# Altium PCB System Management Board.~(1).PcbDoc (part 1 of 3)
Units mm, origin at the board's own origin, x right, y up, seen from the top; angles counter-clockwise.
Board outline 150 x 110 mm, 4 copper layers (F.Cu, In1.Cu, In2.Cu, B.Cu); 151 components, 121 nets, 513 pads, 536 vias.
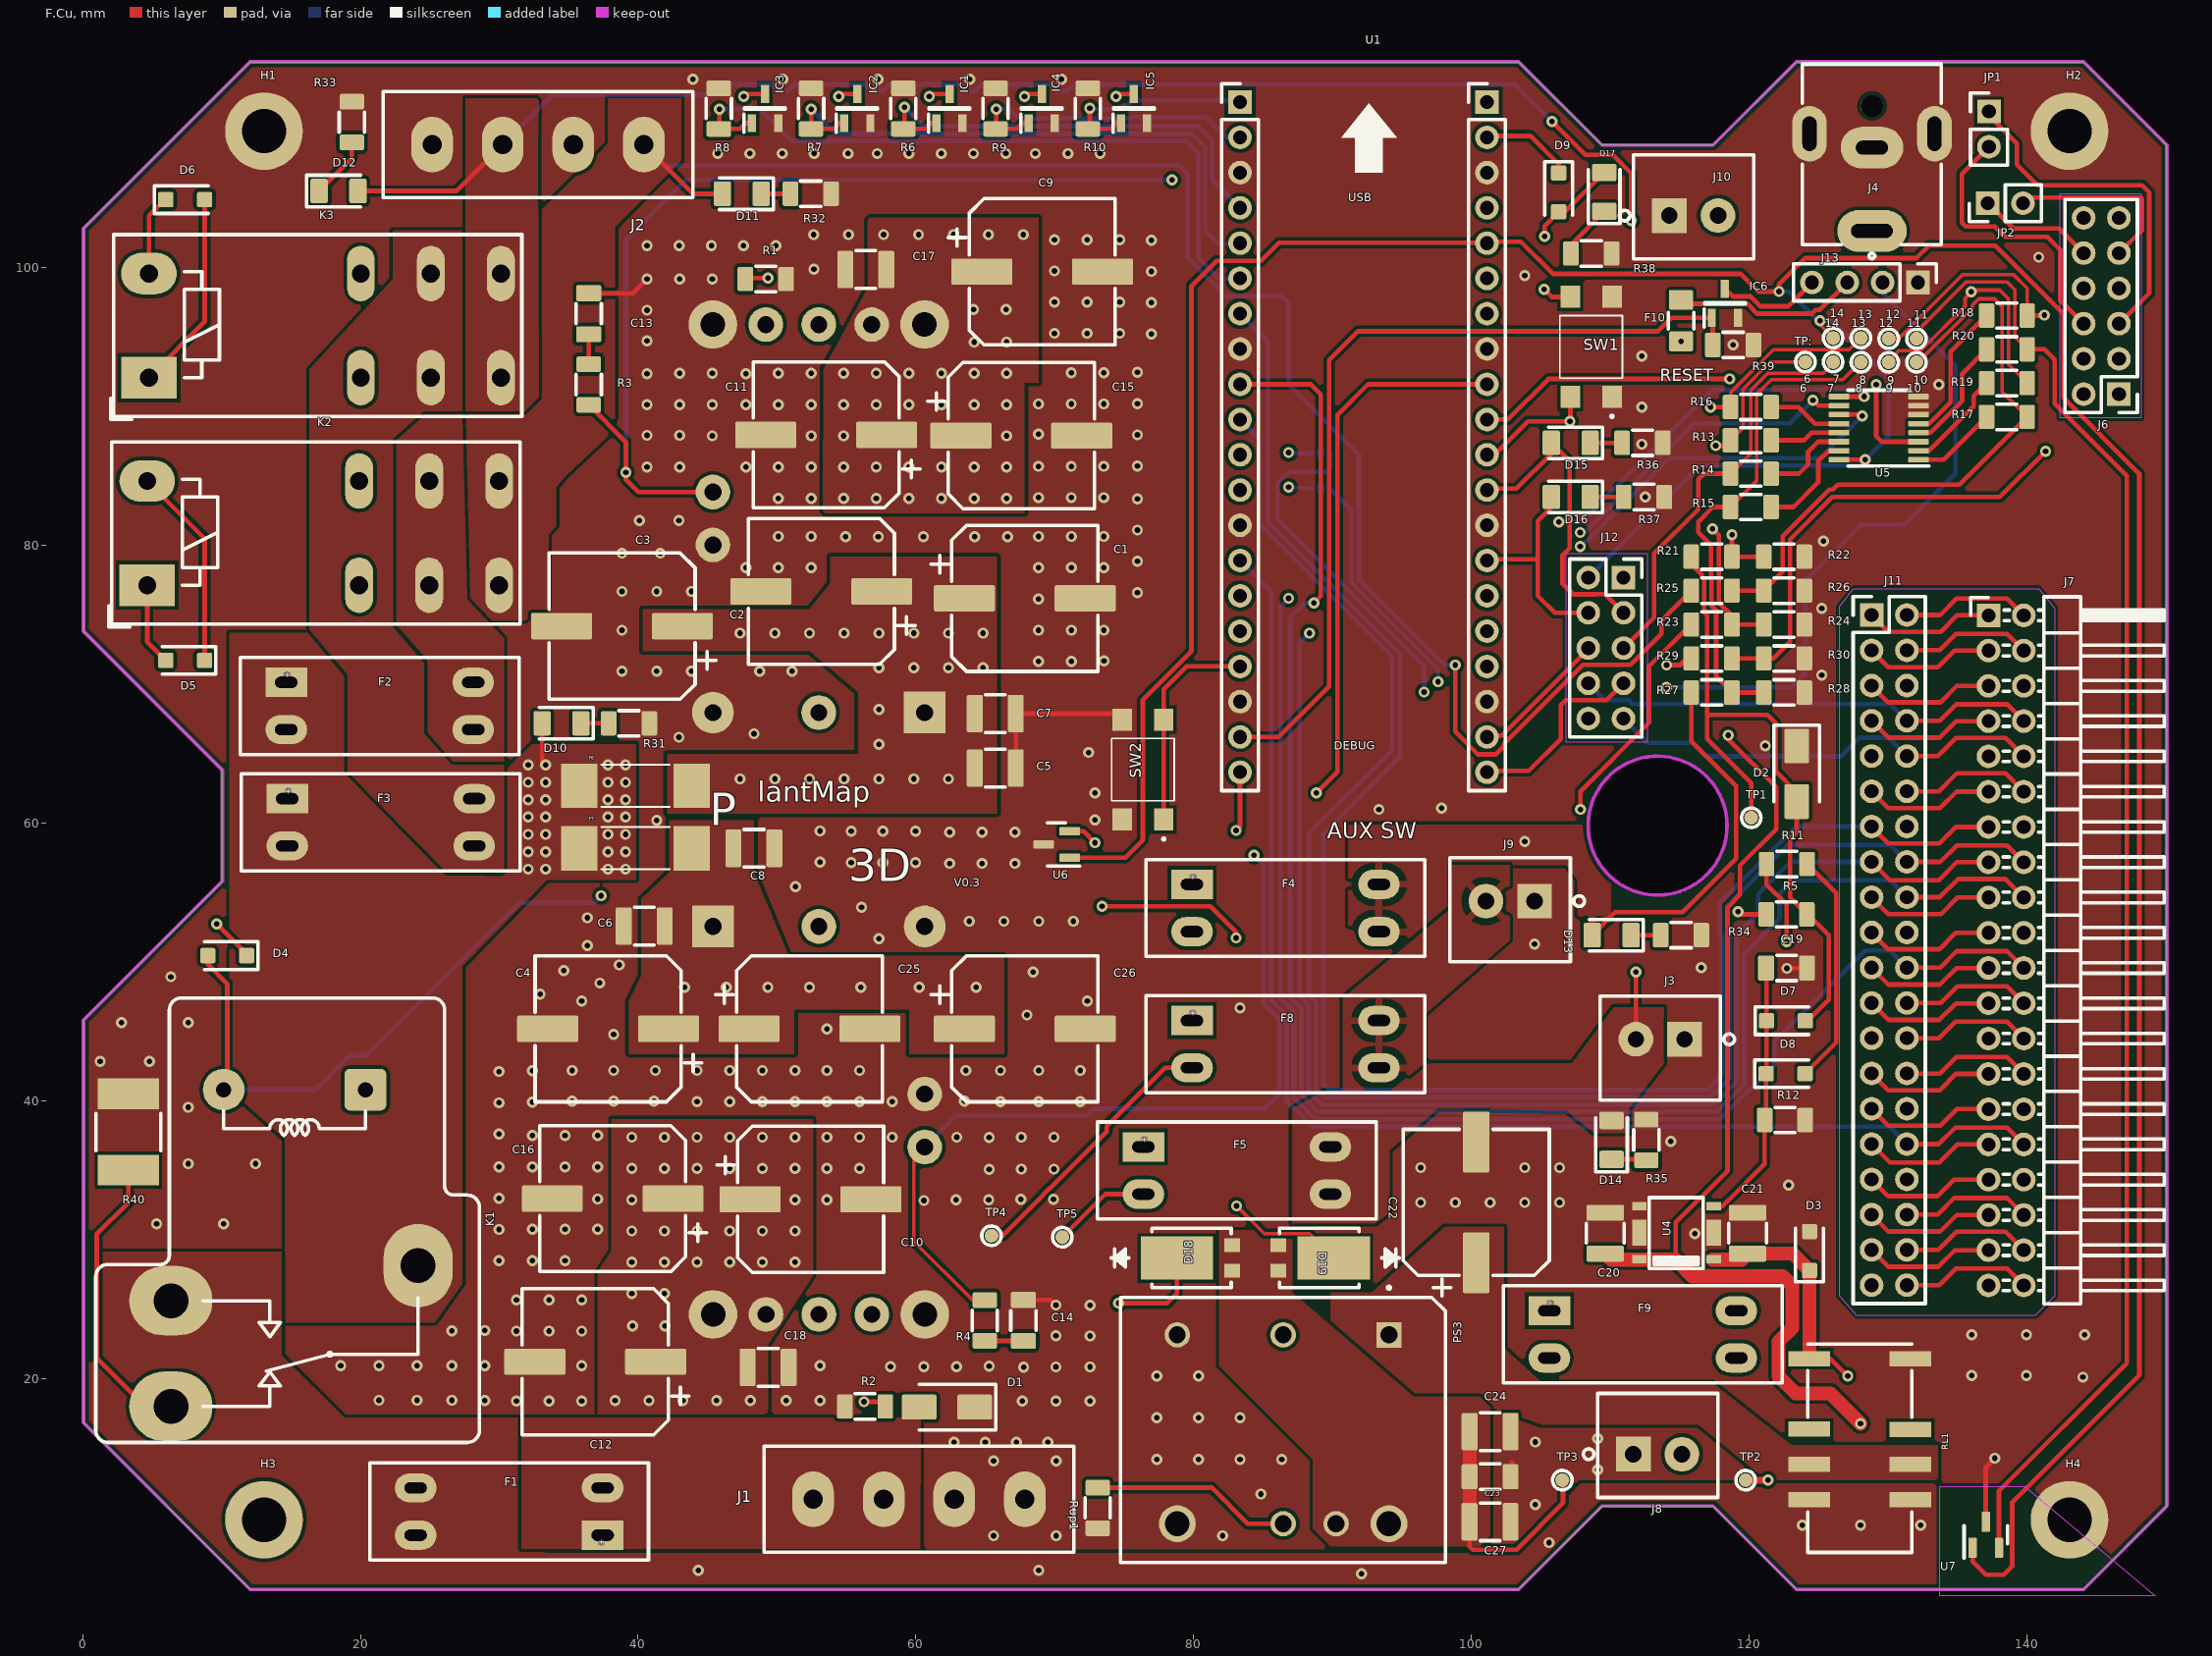
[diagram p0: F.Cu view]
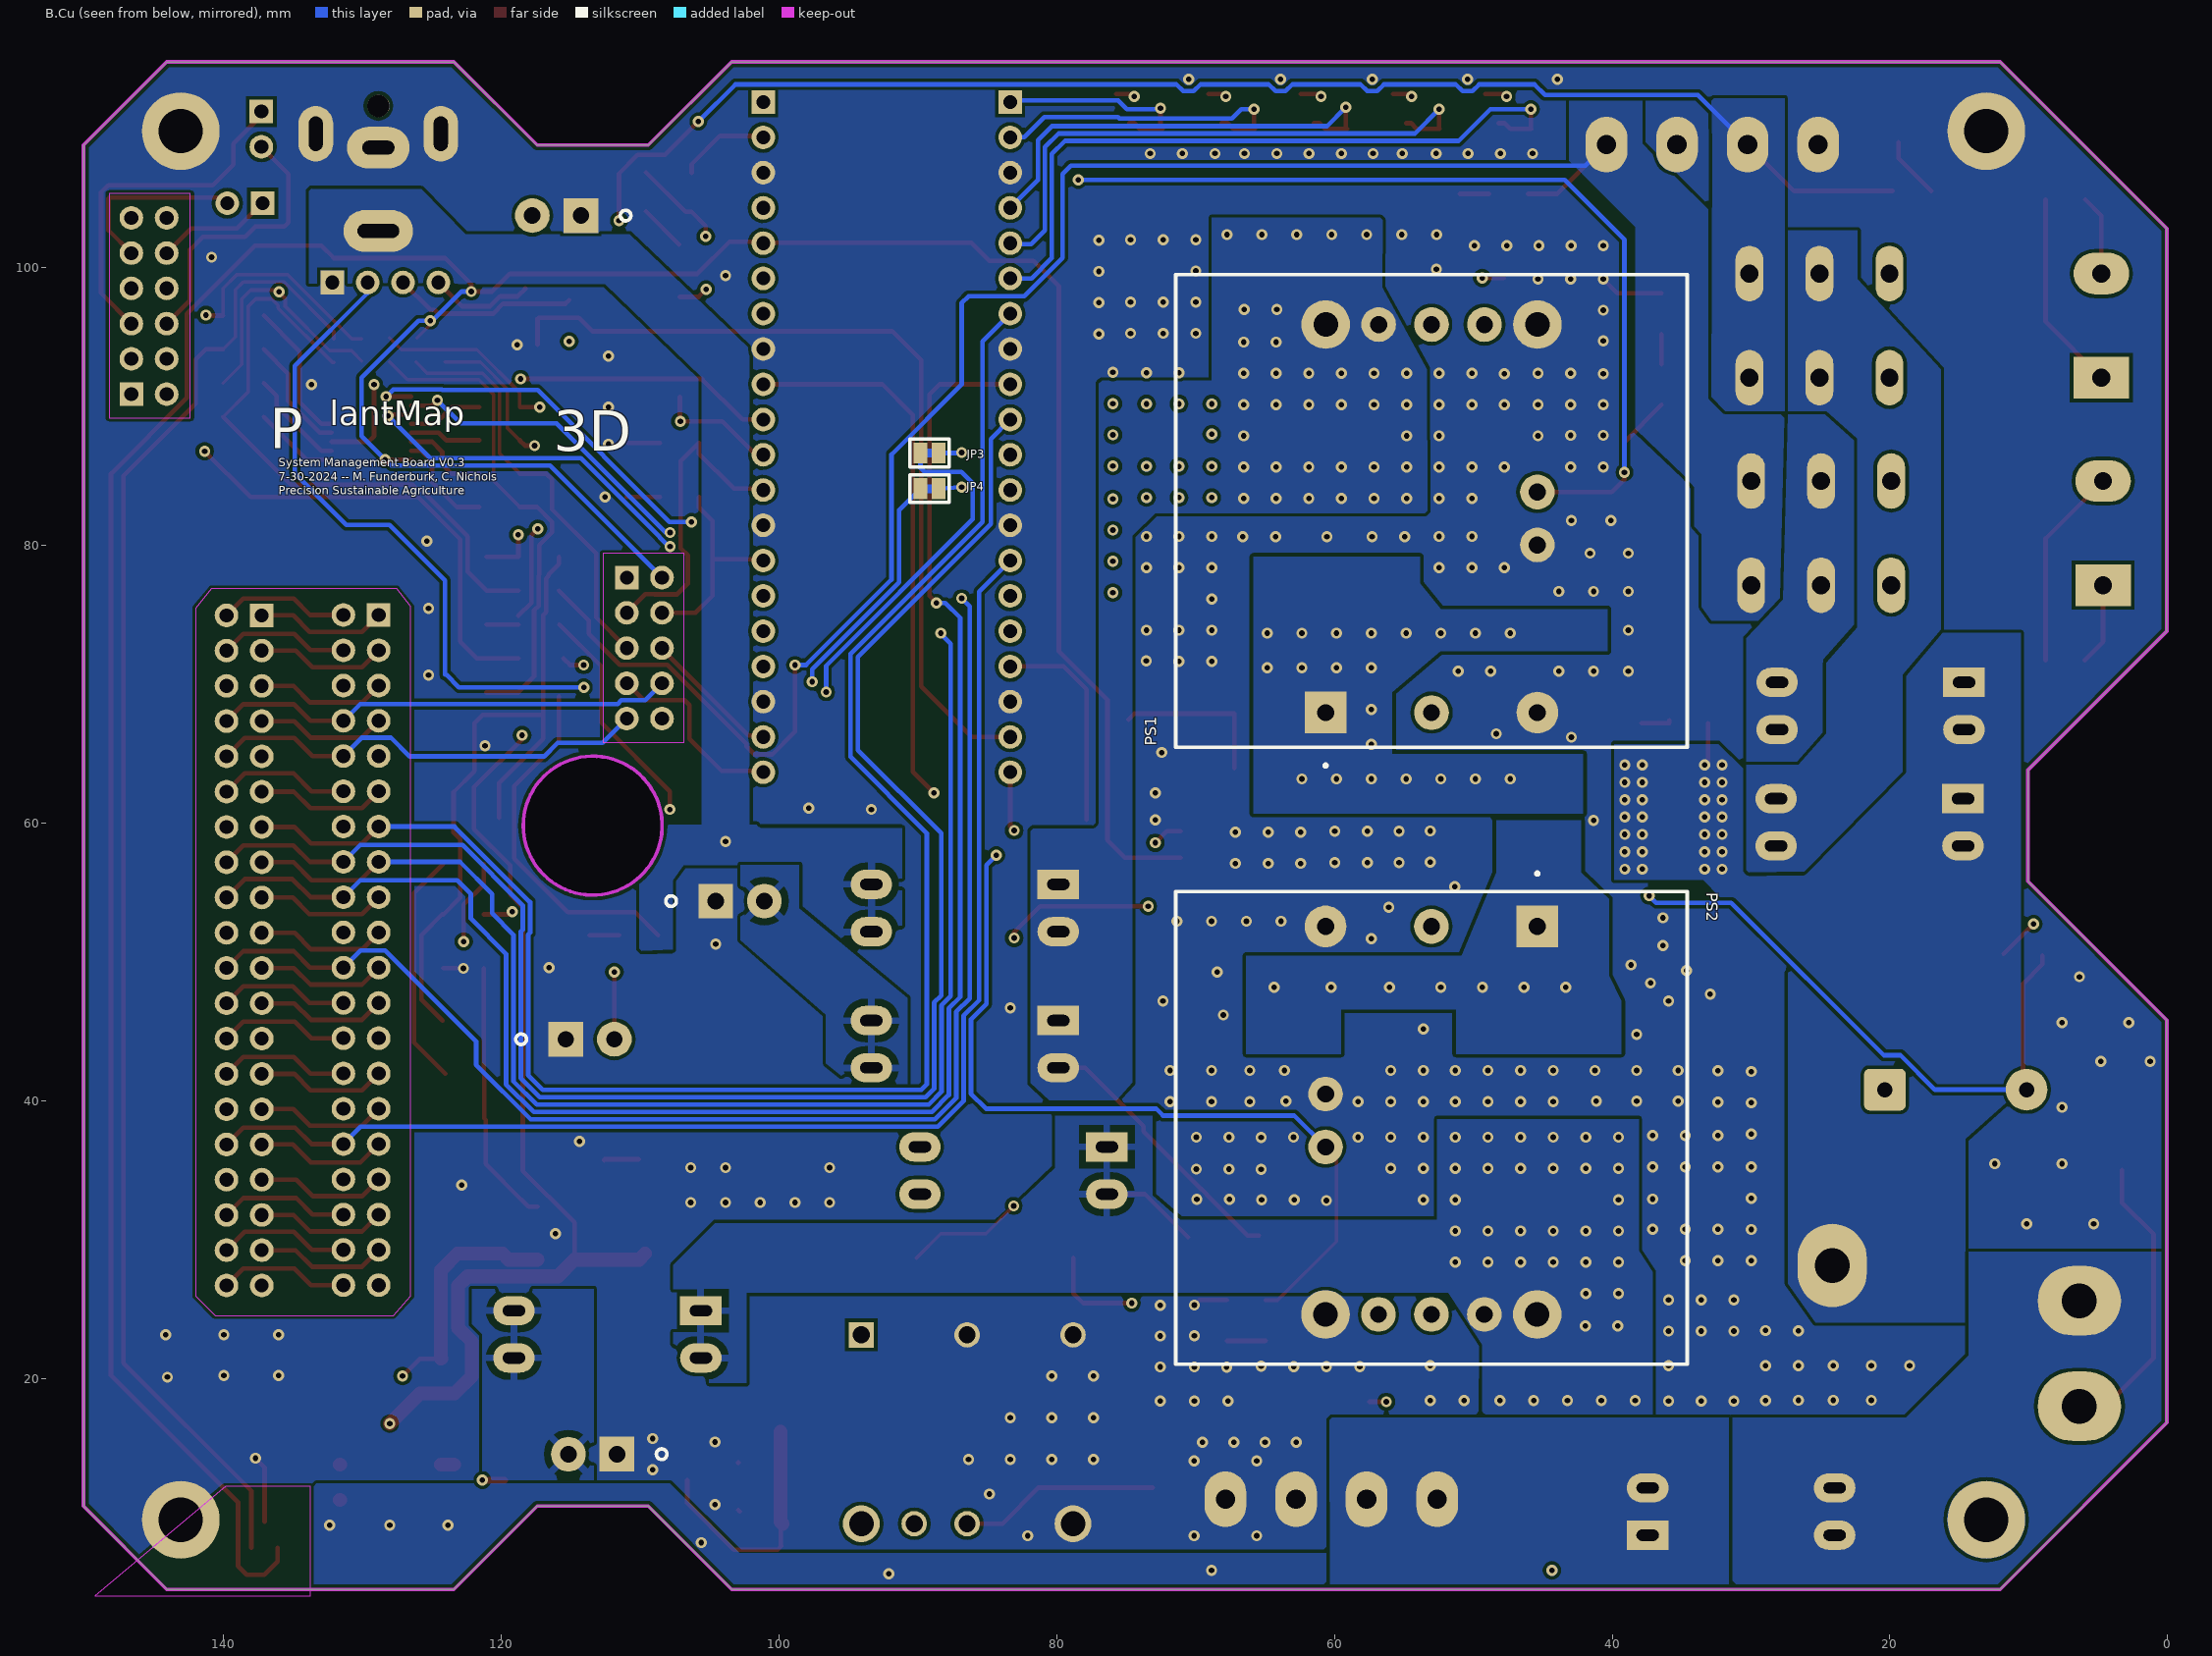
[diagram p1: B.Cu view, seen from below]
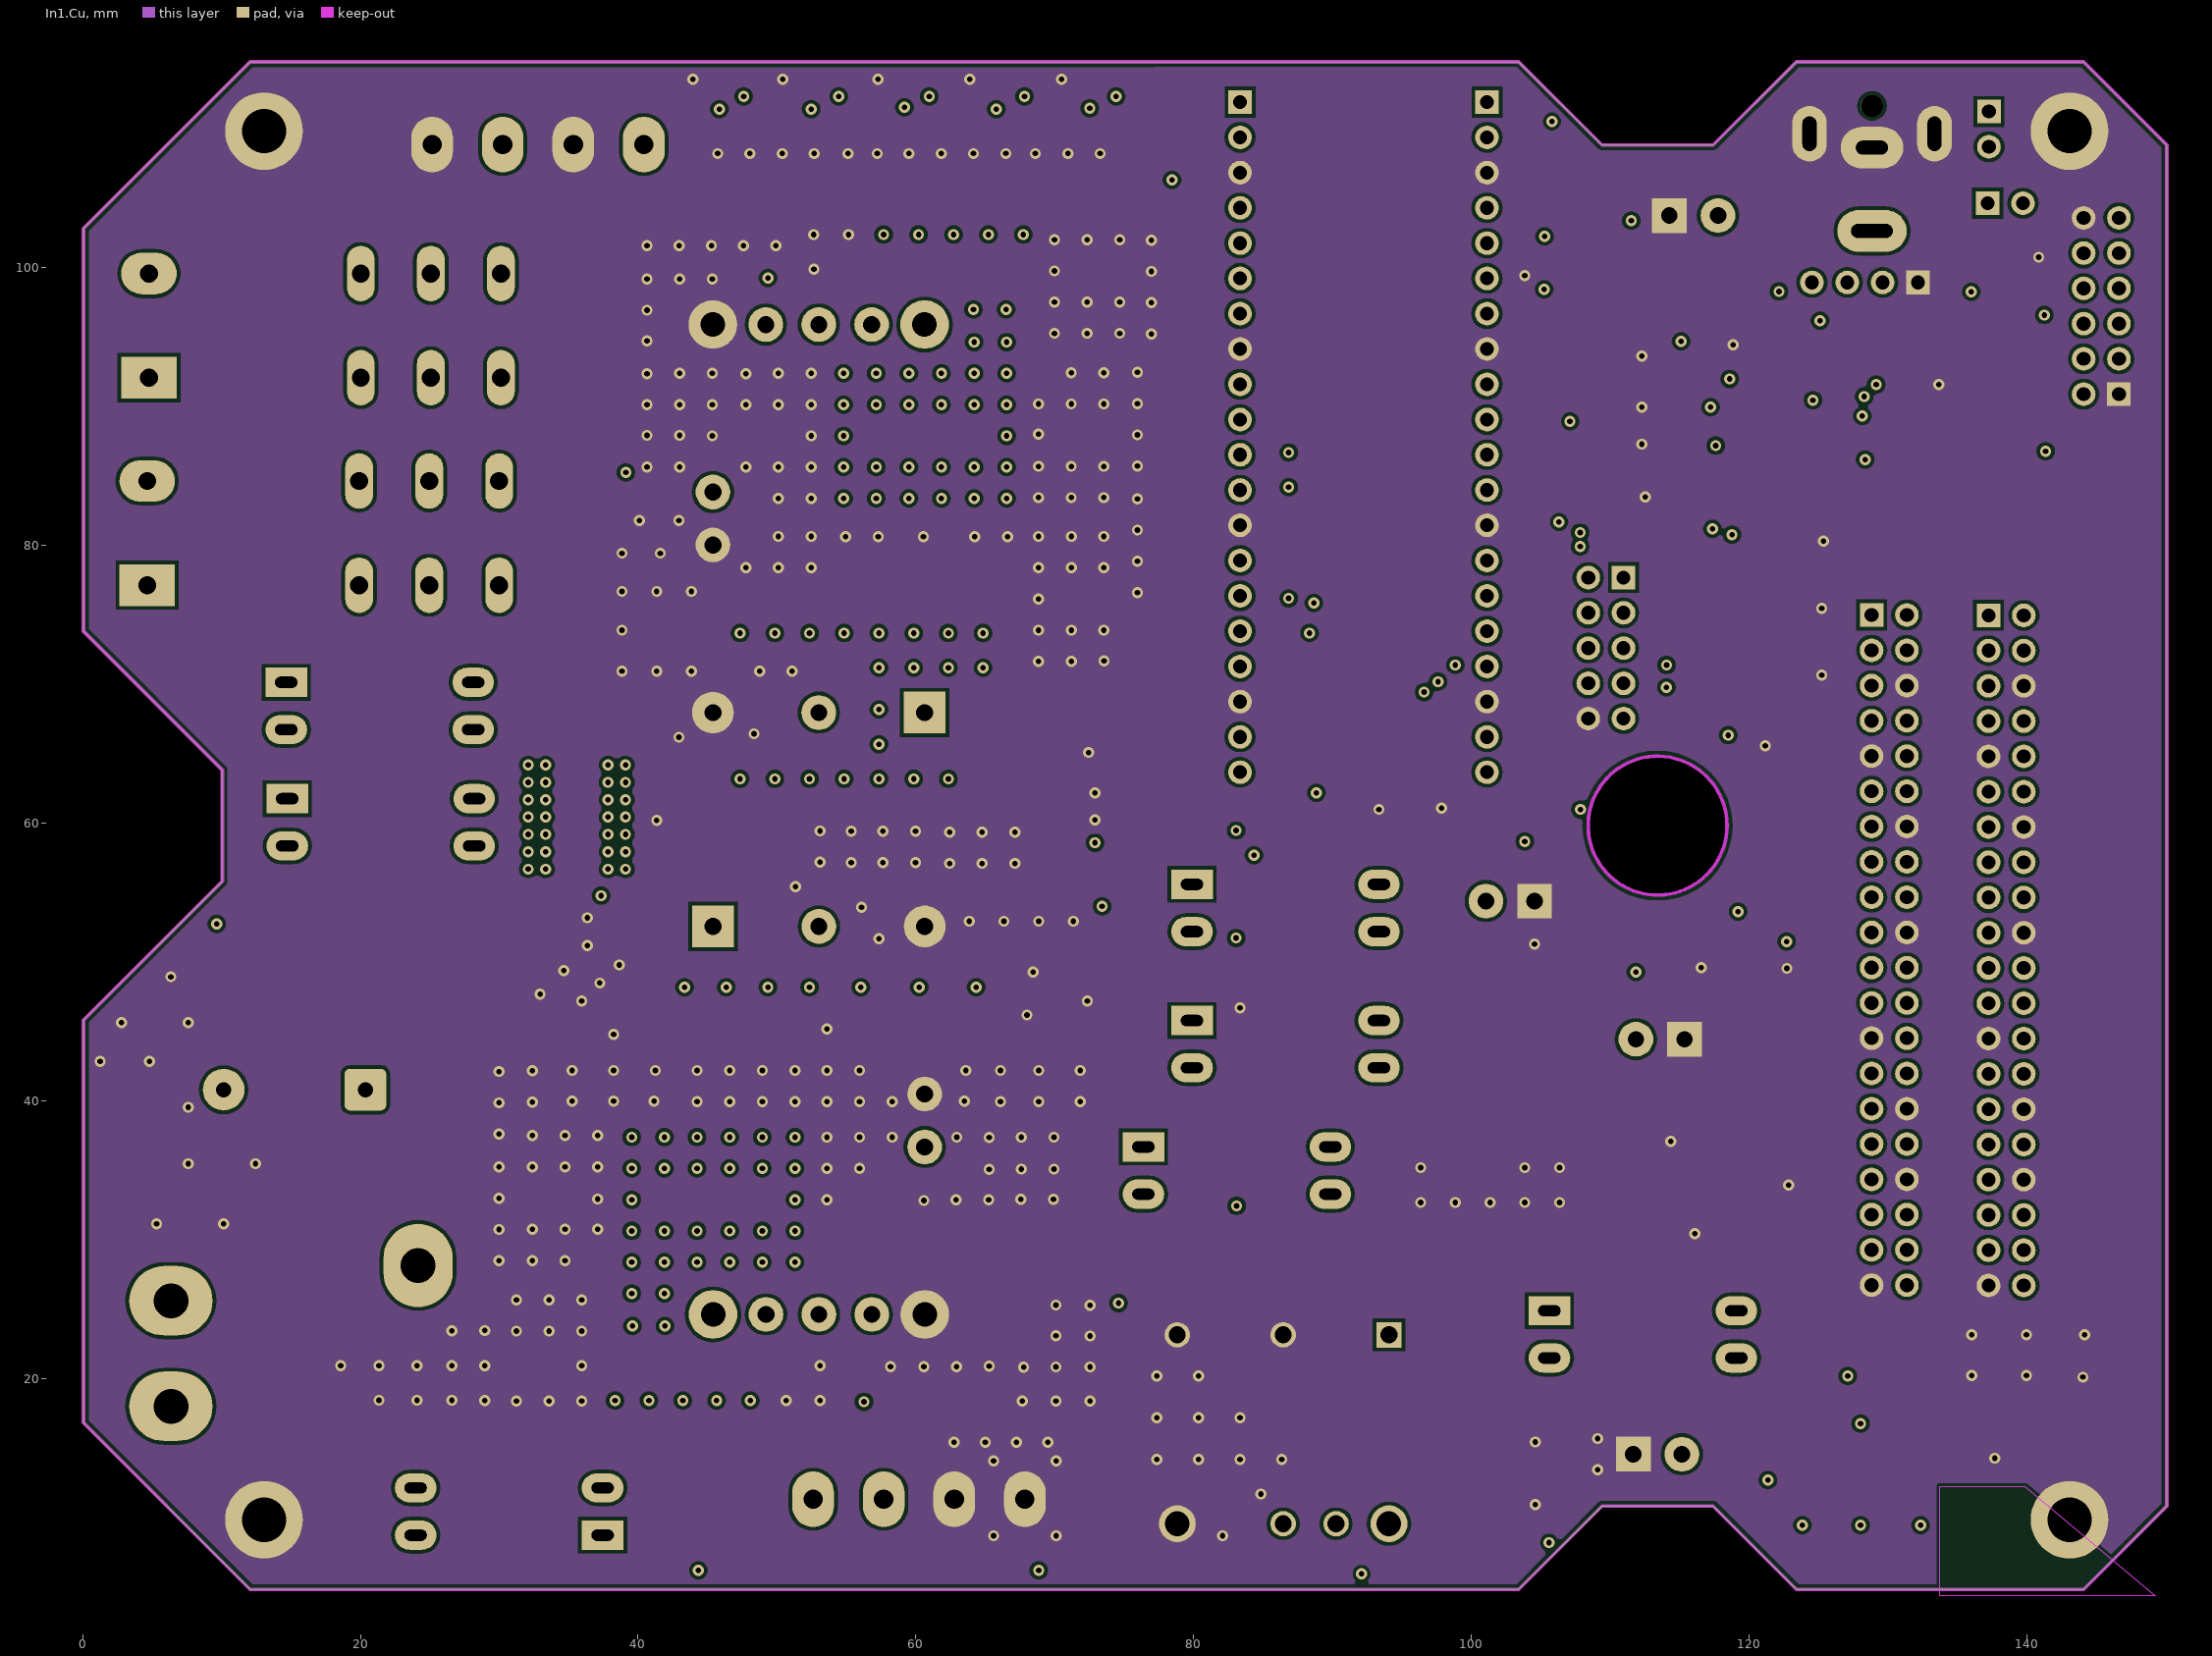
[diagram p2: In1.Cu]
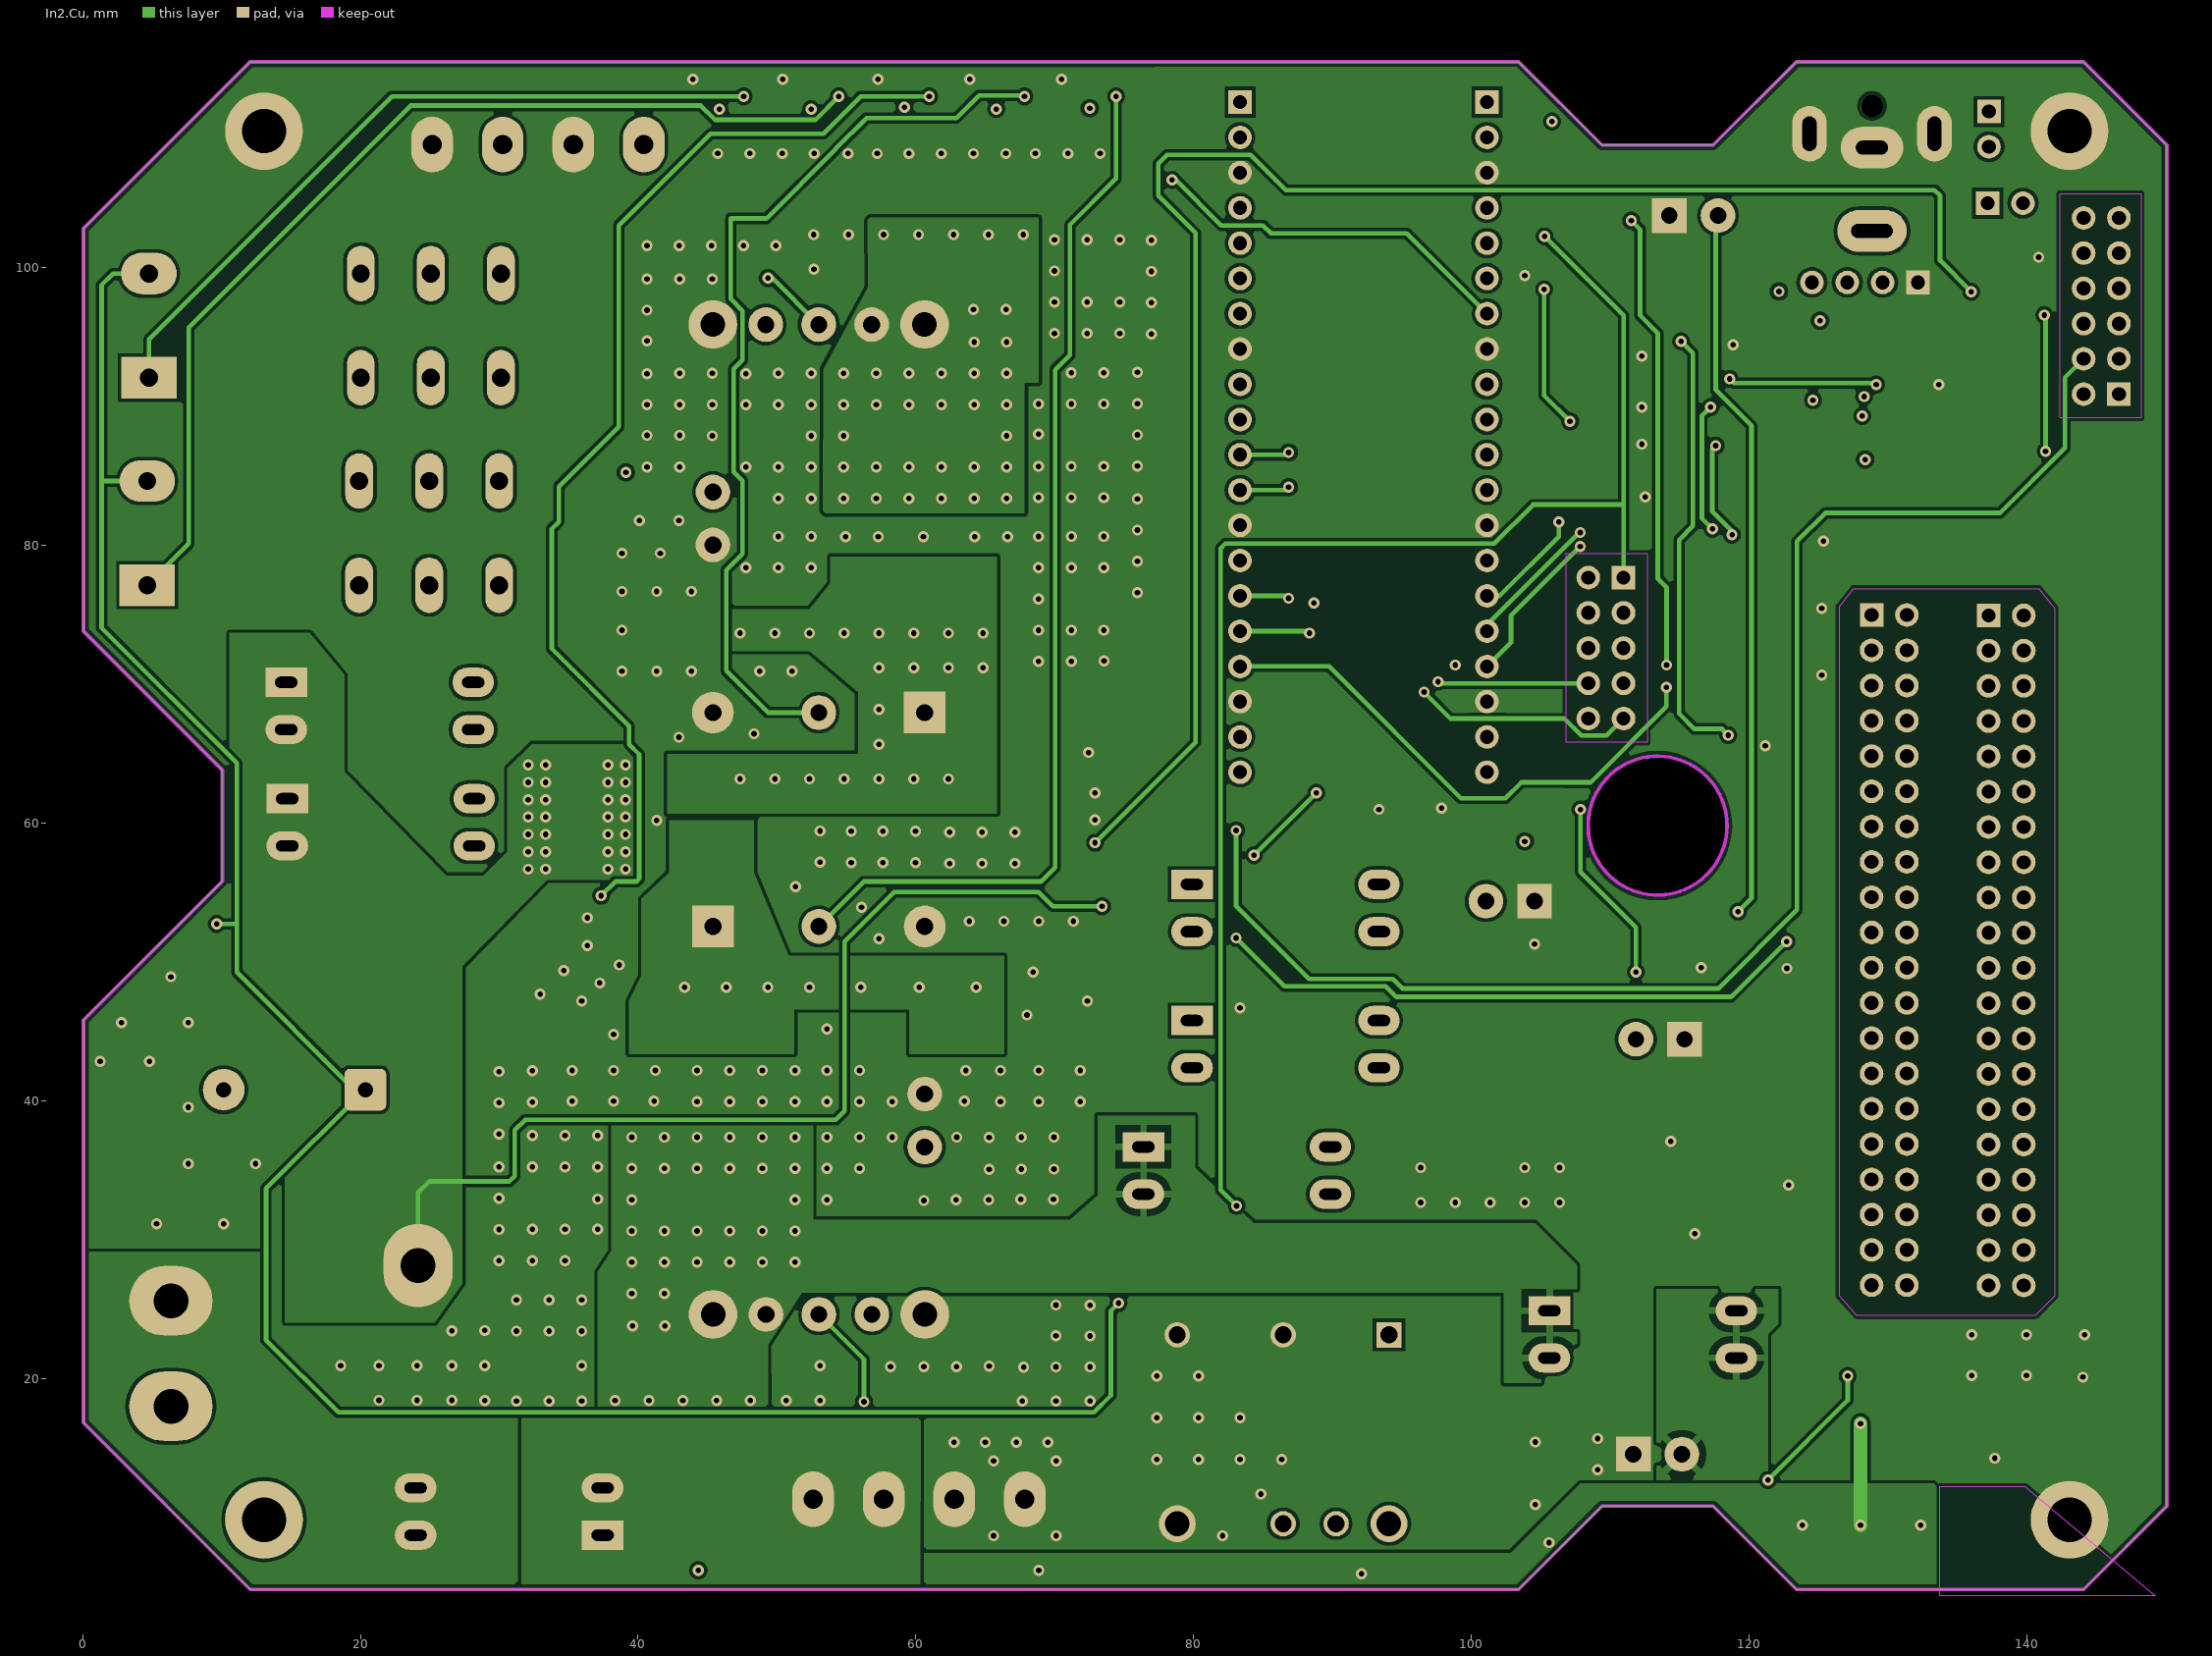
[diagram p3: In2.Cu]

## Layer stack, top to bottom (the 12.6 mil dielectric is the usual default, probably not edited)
F.Mask: solder mask 0.0102, Solder Resist, Dk 3.5
F.Cu: signal copper 0.0356
Dielectric 1: dielectric 0.32, FR-4, Dk 4.8
In1.Cu: signal copper 0.0356
Dielectric2: dielectric 0.32, FR-4, Dk 4.8
In2.Cu: signal copper 0.0356
Dielectric3: dielectric 0.32, FR-4, Dk 4.8
B.Cu: signal copper 0.0356
B.Mask: solder mask 0.0102, Solder Resist, Dk 3.5

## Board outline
109.398,10.821 117.398,10.821 123.398,4.821 144.065,4.821 150.065,10.821 150.065,108.821 144.065,114.821 123.398,114.821 117.398,108.821 109.398,108.821 103.398,114.821 12.065,114.821 0.065,102.821 0.065,73.821 10.065,63.821 10.065,55.821 0.065,45.821 0.065,16.821 12.065,4.821 103.398,4.821 109.398,10.821
cut-out: 108.388,59.821 108.43,59.167 108.558,58.525 108.769,57.904 109.059,57.316 109.423,56.771 109.855,56.278 110.348,55.846 110.893,55.482 111.481,55.192 112.101,54.981 112.744,54.854 113.398,54.811 114.052,54.854 114.695,54.981 115.316,55.192 115.904,55.482 116.449,55.846 116.941,56.278 117.374,56.771 117.738,57.316 118.028,57.904 118.238,58.525 118.366,59.167 118.409,59.821 118.366,60.475 118.238,61.118 118.028,61.739 117.738,62.327 117.374,62.872 116.941,63.365 116.449,63.797 115.904,64.161 115.316,64.451 114.695,64.661 114.052,64.789 113.398,64.832 112.744,64.789 112.101,64.661 111.481,64.451 110.893,64.161 110.348,63.797 109.855,63.365 109.423,62.872 109.059,62.327 108.769,61.739 108.558,61.118 108.43,60.475 108.388,59.821

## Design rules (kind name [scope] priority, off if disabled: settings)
Clearance "Clearence 0.254_Polygon" [InNamedPolygon('F.Cu-/5V Intermediate') OR InNamedPolygon('F.Cu-/i3_Vin') OR InNamedPolygon('F.Cu-/SWITCH PWR OUT PROT') OR InNamedPolygon('F.Cu-GND') OR InNamedPolygon('In2.Cu-GND') OR InNamedPolygon('B.Cu-GND') OR InNamedPolygon('F.Cu-/15v PWR') OR InNamedPolygon('In2.Cu-/15v PWR') OR InNamedPolygon('B.Cu-/15v PWR') OR InNamedPolygon('F.Cu-GND-1') OR InNamedPolygon('In2.Cu-GND-1') OR InNamedPolygon('B.Cu-GND-1') OR InNamedPolygon('F.Cu-/48V PWR') OR InNamedPolygon('In2.Cu-/48V PWR') OR InNamedPolygon('B.Cu-/48V PWR') OR InNamedPolygon('F.Cu-/V_batt+') OR InNamedPolygon('In2.Cu-/V_batt+') OR InNamedPolygon('B.Cu-/V_batt+') OR InNamedPolygon('F.Cu-/V_batt+ PROT') OR InNamedPolygon('In2.Cu-/V_batt+ PROT') OR InNamedPolygon('B.Cu-/V_batt+ PROT') OR InNamedPolygon('F.Cu-/V_batt+ PROT SW') OR InNamedPolygon('In2.Cu-/V_batt+ PROT SW') OR InNamedPolygon('B.Cu-/V_batt+ PROT SW') OR InNamedPolygon('F.Cu-/CPS_IN_PROT') OR InNamedPolygon('In2.Cu-/CPS_IN_PROT') OR InNamedPolygon('B.Cu-/CPS_IN_PROT') OR InNamedPolygon('F.Cu-/V_batt+ PROT-1') OR InNamedPolygon('In2.Cu-/V_batt+ PROT-1') OR InNamedPolygon('B.Cu-/V_batt+ PROT-1') OR InNamedPolygon('F.Cu-/PSPS_IN_PROT') OR InNamedPolygon('In2.Cu-/PSPS_IN_PROT') OR InNamedPolygon('B.Cu-/PSPS_IN_PROT') OR InNamedPolygon('F.Cu-/15V Aux PWR OUT PROT') OR InNamedPolygon('B.Cu-/15V Aux PWR OUT PROT') OR InNamedPolygon('F.Cu-/LIGHT BANK A PROT') OR InNamedPolygon('B.Cu-/LIGHT BANK A PROT') OR InNamedPolygon('F.Cu-/LIGHT BANK A PROT SW') OR InNamedPolygon('B.Cu-/LIGHT BANK A PROT SW') OR InNamedPolygon('F.Cu-/LIGHT BANK B PROT SW') OR InNamedPolygon('B.Cu-/LIGHT BANK B PROT SW') OR InNamedPolygon('F.Cu-/COMP PWR OUT PROT') OR InNamedPolygon('B.Cu-/COMP PWR OUT PROT') OR InNamedPolygon('F.Cu-/LIGHT BANK B PROT') OR InNamedPolygon('B.Cu-/LIGHT BANK B PROT') OR InNamedPolygon('In1.Cu-GND') OR InNamedPolygon('In2.Cu-GND-3') OR InNamedPolygon('In2.Cu-/48V Aux PWR OUT PROT') OR InNamedPolygon('B.Cu-/48V Aux PWR OUT PROT') OR InNamedPolygon('In2.Cu-/48V PWR-1') OR InNamedPolygon('B.Cu-/48V PWR-1') OR InNamedPolygon('B.Cu-/COMP PWR OUT PROT-1') OR InNamedPolygon('B.Cu-/15v PWR-1')] p1: gap=0.254 ignorepadtopadclearanceinfootprint=FALSE
Clearance "Clearence 0.25_Polygon" [InNamedPolygon('In1.Cu-GND-1') OR InNamedPolygon('In2.Cu-GND-2') OR InNamedPolygon('B.Cu-GND-2')] p2: gap=0.25 ignorepadtopadclearanceinfootprint=FALSE
ComponentClearance [All] p1: gap=0.06 collisioncheckmode=3 verticalgap=0.06 showdistances=FALSE
HoleSize [All] p1: absolutevalues=TRUE maxlimit=4 minlimit=0.025 maxpercent=80.000 minpercent=20.000
MinimumSolderMaskSliver [All] p1: minsoldermaskwidth=0
PolygonConnect "Polygon_B.Cu-/15v PWR-1_ConnectDirect" [IsNamedPolygon('B.Cu-/15v PWR-1')] p1: connectstyle=Direct reliefconductorwidth=0.254 reliefentries=4 polygonreliefangle="90 Angle" airgapwidth=0.254
PolygonConnect "Polygon_B.Cu-/COMP PWR OUT PROT-1_ConnectDirect" [IsNamedPolygon('B.Cu-/COMP PWR OUT PROT-1')] p2: connectstyle=Direct reliefconductorwidth=0.254 reliefentries=4 polygonreliefangle="90 Angle" airgapwidth=0.254
PolygonConnect "Polygon_B.Cu-/48V PWR-1_ConnectDirect" [IsNamedPolygon('B.Cu-/48V PWR-1') vs IsVia] p3: connectstyle=Direct reliefconductorwidth=0.254 reliefentries=4 polygonreliefangle="90 Angle" airgapwidth=0.254
PolygonConnect "Polygon_B.Cu-/48V PWR-1_ConnectRelief45" [IsNamedPolygon('B.Cu-/48V PWR-1') vs (IsThruPin or IsSMTPin) and (PadShape_AllLayers = 'Round')] p4: connectstyle=Relief reliefconductorwidth=0.5 reliefentries=4 polygonreliefangle="45 Angle" airgapwidth=0.5
PolygonConnect "Polygon_B.Cu-/48V PWR-1_ConnectRelief90" [IsNamedPolygon('B.Cu-/48V PWR-1') vs (IsThruPin or IsSMTPin) and (PadShape_AllLayers <> 'Round')] p5: connectstyle=Relief reliefconductorwidth=0.5 reliefentries=4 polygonreliefangle="90 Angle" airgapwidth=0.5
PolygonConnect "Polygon_In2.Cu-/48V PWR-1_ConnectDirect" [IsNamedPolygon('In2.Cu-/48V PWR-1') vs IsVia] p6: connectstyle=Direct reliefconductorwidth=0.254 reliefentries=4 polygonreliefangle="90 Angle" airgapwidth=0.254
PolygonConnect "Polygon_In2.Cu-/48V PWR-1_ConnectRelief45" [IsNamedPolygon('In2.Cu-/48V PWR-1') vs (IsThruPin or IsSMTPin) and (PadShape_AllLayers = 'Round')] p7: connectstyle=Relief reliefconductorwidth=0.5 reliefentries=4 polygonreliefangle="45 Angle" airgapwidth=0.5
PolygonConnect "Polygon_In2.Cu-/48V PWR-1_ConnectRelief90" [IsNamedPolygon('In2.Cu-/48V PWR-1') vs (IsThruPin or IsSMTPin) and (PadShape_AllLayers <> 'Round')] p8: connectstyle=Relief reliefconductorwidth=0.5 reliefentries=4 polygonreliefangle="90 Angle" airgapwidth=0.5
PolygonConnect "Polygon_B.Cu-/48V Aux PWR OUT PROT_ConnectDirect" [IsNamedPolygon('B.Cu-/48V Aux PWR OUT PROT') vs IsVia] p9: connectstyle=Direct reliefconductorwidth=0.254 reliefentries=4 polygonreliefangle="90 Angle" airgapwidth=0.254
PolygonConnect "Polygon_B.Cu-/48V Aux PWR OUT PROT_ConnectRelief45" [IsNamedPolygon('B.Cu-/48V Aux PWR OUT PROT') vs (IsThruPin or IsSMTPin) and (PadShape_AllLayers = 'Round')] p10: connectstyle=Relief reliefconductorwidth=0.5 reliefentries=4 polygonreliefangle="45 Angle" airgapwidth=0.5
PolygonConnect "Polygon_B.Cu-/48V Aux PWR OUT PROT_ConnectRelief90" [IsNamedPolygon('B.Cu-/48V Aux PWR OUT PROT') vs (IsThruPin or IsSMTPin) and (PadShape_AllLayers <> 'Round')] p11: connectstyle=Relief reliefconductorwidth=0.5 reliefentries=4 polygonreliefangle="90 Angle" airgapwidth=0.5
PolygonConnect "Polygon_In2.Cu-/48V Aux PWR OUT PROT_ConnectDirect" [IsNamedPolygon('In2.Cu-/48V Aux PWR OUT PROT') vs IsVia] p12: connectstyle=Direct reliefconductorwidth=0.254 reliefentries=4 polygonreliefangle="90 Angle" airgapwidth=0.254
PolygonConnect "Polygon_In2.Cu-/48V Aux PWR OUT PROT_ConnectRelief45" [IsNamedPolygon('In2.Cu-/48V Aux PWR OUT PROT') vs (IsThruPin or IsSMTPin) and (PadShape_AllLayers = 'Round')] p13: connectstyle=Relief reliefconductorwidth=0.5 reliefentries=4 polygonreliefangle="45 Angle" airgapwidth=0.5
PolygonConnect "Polygon_In2.Cu-/48V Aux PWR OUT PROT_ConnectRelief90" [IsNamedPolygon('In2.Cu-/48V Aux PWR OUT PROT') vs (IsThruPin or IsSMTPin) and (PadShape_AllLayers <> 'Round')] p14: connectstyle=Relief reliefconductorwidth=0.5 reliefentries=4 polygonreliefangle="90 Angle" airgapwidth=0.5
PolygonConnect Polygon_In2.Cu-GND-3_ConnectDirect [IsNamedPolygon('In2.Cu-GND-3') vs IsVia] p15: connectstyle=Direct reliefconductorwidth=0.254 reliefentries=4 polygonreliefangle="90 Angle" airgapwidth=0.254
PolygonConnect Polygon_In2.Cu-GND-3_ConnectRelief45 [IsNamedPolygon('In2.Cu-GND-3') vs (IsThruPin or IsSMTPin) and (PadShape_AllLayers = 'Round')] p16: connectstyle=Relief reliefconductorwidth=0.5 reliefentries=4 polygonreliefangle="45 Angle" airgapwidth=0.5
PolygonConnect Polygon_In2.Cu-GND-3_ConnectRelief90 [IsNamedPolygon('In2.Cu-GND-3') vs (IsThruPin or IsSMTPin) and (PadShape_AllLayers <> 'Round')] p17: connectstyle=Relief reliefconductorwidth=0.5 reliefentries=4 polygonreliefangle="90 Angle" airgapwidth=0.5
PolygonConnect Polygon_B.Cu-GND-2_ConnectDirect [IsNamedPolygon('B.Cu-GND-2') vs IsVia] p18: connectstyle=Direct reliefconductorwidth=0.254 reliefentries=4 polygonreliefangle="90 Angle" airgapwidth=0.254
PolygonConnect Polygon_B.Cu-GND-2_ConnectRelief45 [IsNamedPolygon('B.Cu-GND-2') vs (IsThruPin or IsSMTPin) and (PadShape_AllLayers = 'Round')] p19: connectstyle=Relief reliefconductorwidth=0.508 reliefentries=4 polygonreliefangle="45 Angle" airgapwidth=0.508
PolygonConnect Polygon_B.Cu-GND-2_ConnectRelief90 [IsNamedPolygon('B.Cu-GND-2') vs (IsThruPin or IsSMTPin) and (PadShape_AllLayers <> 'Round')] p20: connectstyle=Relief reliefconductorwidth=0.508 reliefentries=4 polygonreliefangle="90 Angle" airgapwidth=0.508
PolygonConnect Polygon_In2.Cu-GND-2_ConnectDirect [IsNamedPolygon('In2.Cu-GND-2') vs IsVia] p21: connectstyle=Direct reliefconductorwidth=0.254 reliefentries=4 polygonreliefangle="90 Angle" airgapwidth=0.254
PolygonConnect Polygon_In2.Cu-GND-2_ConnectRelief45 [IsNamedPolygon('In2.Cu-GND-2') vs (IsThruPin or IsSMTPin) and (PadShape_AllLayers = 'Round')] p22: connectstyle=Relief reliefconductorwidth=0.508 reliefentries=4 polygonreliefangle="45 Angle" airgapwidth=0.508
PolygonConnect Polygon_In2.Cu-GND-2_ConnectRelief90 [IsNamedPolygon('In2.Cu-GND-2') vs (IsThruPin or IsSMTPin) and (PadShape_AllLayers <> 'Round')] p23: connectstyle=Relief reliefconductorwidth=0.508 reliefentries=4 polygonreliefangle="90 Angle" airgapwidth=0.508
PolygonConnect Polygon_In1.Cu-GND-1_ConnectDirect [IsNamedPolygon('In1.Cu-GND-1') vs IsVia] p24: connectstyle=Direct reliefconductorwidth=0.254 reliefentries=4 polygonreliefangle="90 Angle" airgapwidth=0.254
PolygonConnect Polygon_In1.Cu-GND-1_ConnectRelief45 [IsNamedPolygon('In1.Cu-GND-1') vs (IsThruPin or IsSMTPin) and (PadShape_AllLayers = 'Round')] p25: connectstyle=Relief reliefconductorwidth=0.508 reliefentries=4 polygonreliefangle="45 Angle" airgapwidth=0.508
PolygonConnect Polygon_In1.Cu-GND-1_ConnectRelief90 [IsNamedPolygon('In1.Cu-GND-1') vs (IsThruPin or IsSMTPin) and (PadShape_AllLayers <> 'Round')] p26: connectstyle=Relief reliefconductorwidth=0.508 reliefentries=4 polygonreliefangle="90 Angle" airgapwidth=0.508
PolygonConnect Polygon_In1.Cu-GND_ConnectDirect [IsNamedPolygon('In1.Cu-GND')] p27: connectstyle=Direct reliefconductorwidth=0.254 reliefentries=4 polygonreliefangle="90 Angle" airgapwidth=0.254
PolygonConnect "Polygon_B.Cu-/LIGHT BANK B PROT_ConnectDirect" [IsNamedPolygon('B.Cu-/LIGHT BANK B PROT')] p28: connectstyle=Direct reliefconductorwidth=0.254 reliefentries=4 polygonreliefangle="90 Angle" airgapwidth=0.254
PolygonConnect "Polygon_F.Cu-/LIGHT BANK B PROT_ConnectDirect" [IsNamedPolygon('F.Cu-/LIGHT BANK B PROT')] p29: connectstyle=Direct reliefconductorwidth=0.254 reliefentries=4 polygonreliefangle="90 Angle" airgapwidth=0.254
PolygonConnect "Polygon_B.Cu-/COMP PWR OUT PROT_ConnectDirect" [IsNamedPolygon('B.Cu-/COMP PWR OUT PROT') vs IsVia] p30: connectstyle=Direct reliefconductorwidth=0.254 reliefentries=4 polygonreliefangle="90 Angle" airgapwidth=0.254
PolygonConnect "Polygon_B.Cu-/COMP PWR OUT PROT_ConnectRelief45" [IsNamedPolygon('B.Cu-/COMP PWR OUT PROT') vs (IsThruPin or IsSMTPin) and (PadShape_AllLayers = 'Round')] p31: connectstyle=Relief reliefconductorwidth=0.5 reliefentries=4 polygonreliefangle="45 Angle" airgapwidth=0.5
PolygonConnect "Polygon_B.Cu-/COMP PWR OUT PROT_ConnectRelief90" [IsNamedPolygon('B.Cu-/COMP PWR OUT PROT') vs (IsThruPin or IsSMTPin) and (PadShape_AllLayers <> 'Round')] p32: connectstyle=Relief reliefconductorwidth=0.5 reliefentries=4 polygonreliefangle="90 Angle" airgapwidth=0.5
PolygonConnect "Polygon_F.Cu-/COMP PWR OUT PROT_ConnectDirect" [IsNamedPolygon('F.Cu-/COMP PWR OUT PROT') vs IsVia] p33: connectstyle=Direct reliefconductorwidth=0.254 reliefentries=4 polygonreliefangle="90 Angle" airgapwidth=0.254
PolygonConnect "Polygon_F.Cu-/COMP PWR OUT PROT_ConnectRelief45" [IsNamedPolygon('F.Cu-/COMP PWR OUT PROT') vs (IsThruPin or IsSMTPin) and (PadShape_AllLayers = 'Round')] p34: connectstyle=Relief reliefconductorwidth=0.5 reliefentries=4 polygonreliefangle="45 Angle" airgapwidth=0.5
PolygonConnect "Polygon_F.Cu-/COMP PWR OUT PROT_ConnectRelief90" [IsNamedPolygon('F.Cu-/COMP PWR OUT PROT') vs (IsThruPin or IsSMTPin) and (PadShape_AllLayers <> 'Round')] p35: connectstyle=Relief reliefconductorwidth=0.5 reliefentries=4 polygonreliefangle="90 Angle" airgapwidth=0.5
PolygonConnect "Polygon_B.Cu-/LIGHT BANK B PROT SW_ConnectDirect" [IsNamedPolygon('B.Cu-/LIGHT BANK B PROT SW')] p36: connectstyle=Direct reliefconductorwidth=0.254 reliefentries=4 polygonreliefangle="90 Angle" airgapwidth=0.254
PolygonConnect "Polygon_F.Cu-/LIGHT BANK B PROT SW_ConnectDirect" [IsNamedPolygon('F.Cu-/LIGHT BANK B PROT SW')] p37: connectstyle=Direct reliefconductorwidth=0.254 reliefentries=4 polygonreliefangle="90 Angle" airgapwidth=0.254
PolygonConnect "Polygon_B.Cu-/LIGHT BANK A PROT SW_ConnectDirect" [IsNamedPolygon('B.Cu-/LIGHT BANK A PROT SW')] p38: connectstyle=Direct reliefconductorwidth=0.254 reliefentries=4 polygonreliefangle="90 Angle" airgapwidth=0.254
PolygonConnect "Polygon_F.Cu-/LIGHT BANK A PROT SW_ConnectDirect" [IsNamedPolygon('F.Cu-/LIGHT BANK A PROT SW')] p39: connectstyle=Direct reliefconductorwidth=0.254 reliefentries=4 polygonreliefangle="90 Angle" airgapwidth=0.254
PolygonConnect "Polygon_B.Cu-/LIGHT BANK A PROT_ConnectDirect" [IsNamedPolygon('B.Cu-/LIGHT BANK A PROT')] p40: connectstyle=Direct reliefconductorwidth=0.254 reliefentries=4 polygonreliefangle="90 Angle" airgapwidth=0.254
PolygonConnect "Polygon_F.Cu-/LIGHT BANK A PROT_ConnectDirect" [IsNamedPolygon('F.Cu-/LIGHT BANK A PROT')] p41: connectstyle=Direct reliefconductorwidth=0.254 reliefentries=4 polygonreliefangle="90 Angle" airgapwidth=0.254
PolygonConnect "Polygon_B.Cu-/15V Aux PWR OUT PROT_ConnectDirect" [IsNamedPolygon('B.Cu-/15V Aux PWR OUT PROT') vs IsVia] p42: connectstyle=Direct reliefconductorwidth=0.254 reliefentries=4 polygonreliefangle="90 Angle" airgapwidth=0.254
PolygonConnect "Polygon_B.Cu-/15V Aux PWR OUT PROT_ConnectRelief45" [IsNamedPolygon('B.Cu-/15V Aux PWR OUT PROT') vs (IsThruPin or IsSMTPin) and (PadShape_AllLayers = 'Round')] p43: connectstyle=Relief reliefconductorwidth=0.5 reliefentries=4 polygonreliefangle="45 Angle" airgapwidth=0.5
PolygonConnect "Polygon_B.Cu-/15V Aux PWR OUT PROT_ConnectRelief90" [IsNamedPolygon('B.Cu-/15V Aux PWR OUT PROT') vs (IsThruPin or IsSMTPin) and (PadShape_AllLayers <> 'Round')] p44: connectstyle=Relief reliefconductorwidth=0.5 reliefentries=4 polygonreliefangle="90 Angle" airgapwidth=0.5
PolygonConnect "Polygon_F.Cu-/15V Aux PWR OUT PROT_ConnectDirect" [IsNamedPolygon('F.Cu-/15V Aux PWR OUT PROT') vs IsVia] p45: connectstyle=Direct reliefconductorwidth=0.254 reliefentries=4 polygonreliefangle="90 Angle" airgapwidth=0.254
PolygonConnect "Polygon_F.Cu-/15V Aux PWR OUT PROT_ConnectRelief45" [IsNamedPolygon('F.Cu-/15V Aux PWR OUT PROT') vs (IsThruPin or IsSMTPin) and (PadShape_AllLayers = 'Round')] p46: connectstyle=Relief reliefconductorwidth=0.5 reliefentries=4 polygonreliefangle="45 Angle" airgapwidth=0.5
PolygonConnect "Polygon_F.Cu-/15V Aux PWR OUT PROT_ConnectRelief90" [IsNamedPolygon('F.Cu-/15V Aux PWR OUT PROT') vs (IsThruPin or IsSMTPin) and (PadShape_AllLayers <> 'Round')] p47: connectstyle=Relief reliefconductorwidth=0.5 reliefentries=4 polygonreliefangle="90 Angle" airgapwidth=0.5
PolygonConnect Polygon_B.Cu-/PSPS_IN_PROT_ConnectDirect [IsNamedPolygon('B.Cu-/PSPS_IN_PROT')] p48: connectstyle=Direct reliefconductorwidth=0.254 reliefentries=4 polygonreliefangle="90 Angle" airgapwidth=0.254
PolygonConnect Polygon_In2.Cu-/PSPS_IN_PROT_ConnectDirect [IsNamedPolygon('In2.Cu-/PSPS_IN_PROT')] p49: connectstyle=Direct reliefconductorwidth=0.254 reliefentries=4 polygonreliefangle="90 Angle" airgapwidth=0.254
PolygonConnect Polygon_F.Cu-/PSPS_IN_PROT_ConnectDirect [IsNamedPolygon('F.Cu-/PSPS_IN_PROT')] p50: connectstyle=Direct reliefconductorwidth=0.254 reliefentries=4 polygonreliefangle="90 Angle" airgapwidth=0.254
PolygonConnect "Polygon_B.Cu-/V_batt+ PROT-1_ConnectDirect" [IsNamedPolygon('B.Cu-/V_batt+ PROT-1')] p51: connectstyle=Direct reliefconductorwidth=0.254 reliefentries=4 polygonreliefangle="90 Angle" airgapwidth=0.254
PolygonConnect "Polygon_In2.Cu-/V_batt+ PROT-1_ConnectDirect" [IsNamedPolygon('In2.Cu-/V_batt+ PROT-1')] p52: connectstyle=Direct reliefconductorwidth=0.254 reliefentries=4 polygonreliefangle="90 Angle" airgapwidth=0.254
PolygonConnect "Polygon_F.Cu-/V_batt+ PROT-1_ConnectDirect" [IsNamedPolygon('F.Cu-/V_batt+ PROT-1')] p53: connectstyle=Direct reliefconductorwidth=0.254 reliefentries=4 polygonreliefangle="90 Angle" airgapwidth=0.254
PolygonConnect Polygon_B.Cu-/CPS_IN_PROT_ConnectDirect [IsNamedPolygon('B.Cu-/CPS_IN_PROT')] p54: connectstyle=Direct reliefconductorwidth=0.254 reliefentries=4 polygonreliefangle="90 Angle" airgapwidth=0.254
PolygonConnect Polygon_In2.Cu-/CPS_IN_PROT_ConnectDirect [IsNamedPolygon('In2.Cu-/CPS_IN_PROT')] p55: connectstyle=Direct reliefconductorwidth=0.254 reliefentries=4 polygonreliefangle="90 Angle" airgapwidth=0.254
PolygonConnect Polygon_F.Cu-/CPS_IN_PROT_ConnectDirect [IsNamedPolygon('F.Cu-/CPS_IN_PROT')] p56: connectstyle=Direct reliefconductorwidth=0.254 reliefentries=4 polygonreliefangle="90 Angle" airgapwidth=0.254
PolygonConnect "Polygon_B.Cu-/V_batt+ PROT SW_ConnectDirect" [IsNamedPolygon('B.Cu-/V_batt+ PROT SW')] p57: connectstyle=Direct reliefconductorwidth=0.254 reliefentries=4 polygonreliefangle="90 Angle" airgapwidth=0.254
PolygonConnect "Polygon_In2.Cu-/V_batt+ PROT SW_ConnectDirect" [IsNamedPolygon('In2.Cu-/V_batt+ PROT SW')] p58: connectstyle=Direct reliefconductorwidth=0.254 reliefentries=4 polygonreliefangle="90 Angle" airgapwidth=0.254
PolygonConnect "Polygon_F.Cu-/V_batt+ PROT SW_ConnectDirect" [IsNamedPolygon('F.Cu-/V_batt+ PROT SW')] p59: connectstyle=Direct reliefconductorwidth=0.254 reliefentries=4 polygonreliefangle="90 Angle" airgapwidth=0.254
PolygonConnect "Polygon_B.Cu-/V_batt+ PROT_ConnectDirect" [IsNamedPolygon('B.Cu-/V_batt+ PROT')] p60: connectstyle=Direct reliefconductorwidth=0.254 reliefentries=4 polygonreliefangle="90 Angle" airgapwidth=0.254
PolygonConnect "Polygon_In2.Cu-/V_batt+ PROT_ConnectDirect" [IsNamedPolygon('In2.Cu-/V_batt+ PROT')] p61: connectstyle=Direct reliefconductorwidth=0.254 reliefentries=4 polygonreliefangle="90 Angle" airgapwidth=0.254
PolygonConnect "Polygon_F.Cu-/V_batt+ PROT_ConnectDirect" [IsNamedPolygon('F.Cu-/V_batt+ PROT')] p62: connectstyle=Direct reliefconductorwidth=0.254 reliefentries=4 polygonreliefangle="90 Angle" airgapwidth=0.254
PolygonConnect Polygon_B.Cu-/V_batt+_ConnectDirect [IsNamedPolygon('B.Cu-/V_batt+')] p63: connectstyle=Direct reliefconductorwidth=0.254 reliefentries=4 polygonreliefangle="90 Angle" airgapwidth=0.254
PolygonConnect Polygon_In2.Cu-/V_batt+_ConnectDirect [IsNamedPolygon('In2.Cu-/V_batt+')] p64: connectstyle=Direct reliefconductorwidth=0.254 reliefentries=4 polygonreliefangle="90 Angle" airgapwidth=0.254
PolygonConnect Polygon_F.Cu-/V_batt+_ConnectDirect [IsNamedPolygon('F.Cu-/V_batt+')] p65: connectstyle=Direct reliefconductorwidth=0.254 reliefentries=4 polygonreliefangle="90 Angle" airgapwidth=0.254
PolygonConnect "Polygon_B.Cu-/48V PWR_ConnectDirect" [IsNamedPolygon('B.Cu-/48V PWR')] p66: connectstyle=Direct reliefconductorwidth=0.254 reliefentries=4 polygonreliefangle="90 Angle" airgapwidth=0.254
PolygonConnect "Polygon_In2.Cu-/48V PWR_ConnectDirect" [IsNamedPolygon('In2.Cu-/48V PWR')] p67: connectstyle=Direct reliefconductorwidth=0.254 reliefentries=4 polygonreliefangle="90 Angle" airgapwidth=0.254
PolygonConnect "Polygon_F.Cu-/48V PWR_ConnectDirect" [IsNamedPolygon('F.Cu-/48V PWR')] p68: connectstyle=Direct reliefconductorwidth=0.254 reliefentries=4 polygonreliefangle="90 Angle" airgapwidth=0.254
PolygonConnect Polygon_B.Cu-GND-1_ConnectDirect [IsNamedPolygon('B.Cu-GND-1')] p69: connectstyle=Direct reliefconductorwidth=0.254 reliefentries=4 polygonreliefangle="90 Angle" airgapwidth=0.254
PolygonConnect Polygon_In2.Cu-GND-1_ConnectDirect [IsNamedPolygon('In2.Cu-GND-1')] p70: connectstyle=Direct reliefconductorwidth=0.254 reliefentries=4 polygonreliefangle="90 Angle" airgapwidth=0.254
PolygonConnect Polygon_F.Cu-GND-1_ConnectDirect [IsNamedPolygon('F.Cu-GND-1')] p71: connectstyle=Direct reliefconductorwidth=0.254 reliefentries=4 polygonreliefangle="90 Angle" airgapwidth=0.254
PolygonConnect "Polygon_B.Cu-/15v PWR_ConnectDirect" [IsNamedPolygon('B.Cu-/15v PWR')] p72: connectstyle=Direct reliefconductorwidth=0.254 reliefentries=4 polygonreliefangle="90 Angle" airgapwidth=0.254
PolygonConnect "Polygon_In2.Cu-/15v PWR_ConnectDirect" [IsNamedPolygon('In2.Cu-/15v PWR')] p73: connectstyle=Direct reliefconductorwidth=0.254 reliefentries=4 polygonreliefangle="90 Angle" airgapwidth=0.254
PolygonConnect "Polygon_F.Cu-/15v PWR_ConnectDirect" [IsNamedPolygon('F.Cu-/15v PWR')] p74: connectstyle=Direct reliefconductorwidth=0.254 reliefentries=4 polygonreliefangle="90 Angle" airgapwidth=0.254
PolygonConnect Polygon_B.Cu-GND_ConnectDirect [IsNamedPolygon('B.Cu-GND')] p75: connectstyle=Direct reliefconductorwidth=0.254 reliefentries=4 polygonreliefangle="90 Angle" airgapwidth=0.254
PolygonConnect Polygon_In2.Cu-GND_ConnectDirect [IsNamedPolygon('In2.Cu-GND')] p76: connectstyle=Direct reliefconductorwidth=0.254 reliefentries=4 polygonreliefangle="90 Angle" airgapwidth=0.254
PolygonConnect Polygon_F.Cu-GND_ConnectDirect [IsNamedPolygon('F.Cu-GND')] p77: connectstyle=Direct reliefconductorwidth=0.254 reliefentries=4 polygonreliefangle="90 Angle" airgapwidth=0.254
PolygonConnect "Polygon_F.Cu-/SWITCH PWR OUT PROT_ConnectDirect" [IsNamedPolygon('F.Cu-/SWITCH PWR OUT PROT')] p78: connectstyle=Direct reliefconductorwidth=0.254 reliefentries=4 polygonreliefangle="90 Angle" airgapwidth=0.254
PolygonConnect Polygon_F.Cu-/i3_Vin_ConnectDirect [IsNamedPolygon('F.Cu-/i3_Vin')] p79: connectstyle=Direct reliefconductorwidth=0.254 reliefentries=4 polygonreliefangle="90 Angle" airgapwidth=0.254
PolygonConnect "Polygon_F.Cu-/5V Intermediate_ConnectDirect" [IsNamedPolygon('F.Cu-/5V Intermediate')] p80: connectstyle=Direct reliefconductorwidth=0.254 reliefentries=4 polygonreliefangle="90 Angle" airgapwidth=0.254
RoutingVias [All] p1: holewidth=0.711 width=1.27 viastyle="Through Hole" minholewidth=0.711 minwidth=1.27 maxholewidth=0.711 maxwidth=1.27
SilkToSilkClearance [All] p1: silktosilkclearance=0
SilkToSolderMaskClearance [IsPad] p1: minsilkscreentomaskgap=0 clearancetoexposedcopper=TRUE
SolderMaskExpansion [All] p1: expansion=0.102 istentingtop=FALSE
SupplyNets "Schematic Supply Nets" [InNet('GND')] p1: voltage=0.000
Width [All] p1: maxlimit=10 minlimit=0.25 preferedwidth=0.25 minimp=50.000000 maximp=50.000000 favimp=50.000000
25 further rules are at their usual default settings.

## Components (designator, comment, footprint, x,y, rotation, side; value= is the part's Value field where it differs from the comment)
6 "Comment" TESTPOINT_PAD_D1.0MM 124.04,93.205 r90 top value=TestPoint (schematic designator TP6)
7 "Comment" TESTPOINT_PAD_D1.0MM 126.04,93.205 r90 top value=TestPoint (schematic designator TP7)
8 "Comment" TESTPOINT_PAD_D1.0MM 128.04,93.187 r90 top value=TestPoint (schematic designator TP8)
9 "Comment" TESTPOINT_PAD_D1.0MM 130.04,93.187 r270 top value=TestPoint (schematic designator TP9)
10 "Comment" TESTPOINT_PAD_D1.0MM 132.04,93.187 r90 top value=TestPoint (schematic designator TP10)
11 "Comment" TESTPOINT_PAD_D1.0MM 132.04,94.887 r90 top value=TestPoint (schematic designator TP11)
12 "Comment" TESTPOINT_PAD_D1.0MM 130.04,94.887 r90 top value=TestPoint (schematic designator TP12)
13 "Comment" TESTPOINT_PAD_D1.0MM 128.04,94.937 r270 top value=TestPoint (schematic designator TP13)
14 "Comment" TESTPOINT_PAD_D1.0MM 126.04,94.937 r90 top value=TestPoint (schematic designator TP14)
C1 "Comment" CP_ELEC_10X12.6 67.84,76.187 r0 top value=180uF
C2 "Comment" CP_ELEC_10X12.6 53.19,76.687 r180 top value=180uF
C3 "Comment" CP_ELEC_10X12.6 38.84,74.187 r180 top value=180uF
C4 "Comment" CP_ELEC_10X12.6 37.84,45.187 r180 top value=180uF
C5 "Comment" C_1210_3225METRIC 65.715,63.962 r0 top value=10uF
C6 "Comment" C_1210_3225METRIC 40.44,52.587 r180 top value=10uF
C7 "Comment" C_1210_3225METRIC 65.715,67.887 r0 top value=10uF
C8 "Comment" C_1210_3225METRIC 48.34,58.187 r0 top value=10uF
C9 "Comment" CP_ELEC_10X12.6 69.09,99.712 r0 top value=100uF
C10 "Comment" CP_ELEC_10X12.6 52.415,32.912 r0 top value=100uF
C11 "Comment" CP_ELEC_10X12.6 53.54,87.962 r180 top value=100uF
C12 "Comment" CP_ELEC_10X12.6 36.915,21.212 r180 top value=100uF
C13 "Comment" C_1206_3216METRIC 36.44,96.687 r90 top value=0.1uF
C14 "Comment" C_1206_3216METRIC 67.74,24.187 r90 top value=0.1uF
C15 "Comment" CP_ELEC_10X12.6 67.59,87.912 r0 top value=100uF
C16 "Comment" CP_ELEC_10X12.6 38.165,32.962 r180 top value=100uF
C17 "Comment" C_1210_3225METRIC 56.39,99.862 r180 top value=0.1uF
C18 "Comment" C_1210_3225METRIC 49.365,20.812 r0 top value=0.1uF
C19 "Comment" C_1206_3216METRIC 122.682,49.57 r0 top value=0.1uF
C20 "Comment" C_1210_3225METRIC 109.627,30.472 r90 top value=10uF
C21 "Comment" C_1210_3225METRIC 119.877,30.472 r90 top value=10uF
C22 "Comment" CP_ELEC_10X12.6 100.34,32.687 r90 top value=100uF
C23 "Comment" C_1206_3216METRIC 101.34,12.937 r0 top value=0.1uF
C24 "Comment" C_1210_3225METRIC 101.34,16.187 r0 top value=10uF
C25 "Comment" CP_ELEC_10X12.6 52.34,45.187 r0 top value=180uF
C26 "Comment" CP_ELEC_10X12.6 67.84,45.187 r0 top value=180uF
C27 "Comment" C_1210_3225METRIC 101.34,9.687 r0 top value=10uF
D1 "Comment" D_SMA 62.23,17.947 r180 top value=D_TVS
D2 "Comment" D_SMA 123.416,63.554 r270 top value=D_TVS
D3 "Comment" D_SOD-123F 124.34,29.187 r90 top value=D
D4 "Comment" D_SOD-123F 10.414,50.459 r180 top value=D
D5 "Comment" D_SOD-123F 7.39,71.718 r180 top value=D
D6 "Comment" D_SOD-123F 7.39,104.903 r0 top value=D
D7 "Comment" D_SOD-123F 122.636,45.77 r0 top value=D
D8 "Comment" D_SOD-123F 122.617,41.96 r0 top value=D
D9 "Comment" D_SOD-123F 106.274,105.424 r270 top value=D
D10 "Comment" LED_1206_3216METRIC 34.484,67.187 r180 top value=RED
D11 "Comment" LED_1206_3216METRIC 47.46,105.321 r180 top value=RED
D12 "Comment" LED_1206_3216METRIC 18.427,105.522 r0 top value=RED
D13 "Comment" LED_1206_3216METRIC 110.09,51.937 r180 top value=RED
D14 "Comment" LED_1206_3216METRIC 110.09,37.187 r90 top value=RED
D15 "Comment" LED_1206_3216METRIC 107.15,87.388 r180 top value=RED
D16 "Comment" LED_1206_3216METRIC 107.15,83.488 r180 top value=RED
D17 "Comment" LED_1206_3216METRIC 109.56,105.462 r90 top value=RED
D18 "Comment" POWERDI5_DIO 79.84,28.687 r90 top value=D5V
D19 "Comment" POWERDI5_DIO 89.036,28.687 r270 top value=D5V
F1 "Comment" 3557-10 37.445,8.725 r180 top value=3557-10
F2 "Comment" 3557-10 14.665,70.142 r0 top value=3557-10
F3 "Comment" 3557-10 14.735,61.762 r0 top value=3557-10
F4 "Comment" 3557-10 79.878,55.59 r0 top value=3557-10
F5 "Comment" 3557-10 76.378,36.687 r0 top value=3557-10
F6 "Comment" FUSC9830X318N 39.805,62.692 r0 top value=Fuse
F7 "Comment" FUSC9830X318N 39.805,58.192 r0 top value=Fuse
F8 "Comment" 3557-10 79.878,45.787 r0 top value=3557-10
F9 "Comment" 3557-10 105.609,24.888 r0 top value=3557-10
F10 "Comment" FUSE_1206_3216METRIC_PAD1.42X1.75MM_HANDSOLDER 115.09,96.187 r90 top value=Fuse
H1 "Comment" MOUNTINGHOLE_3.2MM_M3_DIN965_PAD 13.065,109.837 r0 top value=MountingHole_Pad
H2 "Comment" MOUNTINGHOLE_3.2MM_M3_DIN965_PAD 143.065,109.837 r0 top value=MountingHole_Pad
H3 "Comment" MOUNTINGHOLE_3.2MM_M3_DIN965_PAD 13.065,9.837 r0 top value=MountingHole_Pad
H4 "Comment" MOUNTINGHOLE_3.2MM_M3_DIN965_PAD 143.065,9.837 r0 top value=MountingHole_Pad
IC1 "Comment" SOT95P237X112-3N 62.414,111.457 r90 top value=SI2318CDS-T1-GE3
IC2 "Comment" SOT95P237X112-3N 55.772,111.457 r90 top value=SI2318CDS-T1-GE3
IC3 "Comment" SOT95P237X112-3N 49.129,111.457 r90 top value=SI2318CDS-T1-GE3
IC4 "Comment" SOT95P237X112-3N 69.057,111.457 r90 top value=SI2318CDS-T1-GE3
IC5 "Comment" SOT95P237X112-3N 75.7,111.457 r90 top value=SI2318CDS-T1-GE3
IC6 "Comment" SOT95P237X112-3N 118.252,97.438 r90 top value=SI2318CDS-T1-GE3
J1 "Comment" 1924321 60.22,11.312 r180 top value=Conn_01x04_Male
J2 "Comment" 1924321 32.79,108.862 r180 top value=Conn_01x04_Male
J3 "Comment" 1843606 111.84,44.437 r180 top value=Conn_01x02_Male
J4 "Comment" CUI_PJ-063BH 128.837,102.644 r90 top value=PJ-063BH
J6 "Comment" PINHEADER_2X06_P2.54MM_VERTICAL 146.616,90.891 r180 top value=Conn_02x06_Counter_Clockwise
J7 "Comment" PINHEADER_2X20_P2.54MM_HORIZONTAL 137.227,74.965 r0 top value=Conn_02x20_Odd_Even
J8 "Comment" 1843606 115.152,14.556 r0 top value=Conn_01x02_Male
J9 "Comment" 1843606 101.04,54.387 r180 top value=Conn_01x02_Male
J10 "Comment" 1843606 117.748,103.751 r0 top value=Conn_01x02_Male
J11 "Comment" PINHEADER_2X20_P2.54MM_VERTICAL 128.808,74.991 r0 top value=Conn_02x20_Odd_Even
J12 "Comment" PINSOCKET_2X05_P2.54MM_VERTICAL 110.949,77.686 r0 top value=Conn_02x05_Top_Bottom
J13 "Comment" PINHEADER_1X04_P2.54MM_VERTICAL 132.14,98.937 r270 top value=Conn_01x04_Female
JP1 "Comment" PINHEADER_1X02_P2.54MM_VERTICAL 137.259,111.244 r0 top value=Jumper_2_Open
JP2 "Comment" PINHEADER_1X02_P2.54MM_VERTICAL 137.169,104.64 r90 top value=Jumper_2_Open
JP3 "Comment" SOLDERJUMPER-2_P1.3MM_BRIDGED_PAD1.0X1.5MM 89.15,86.654 r0 bottom value=Jmp_2_Bridged
JP4 "Comment" SOLDERJUMPER-2_P1.3MM_BRIDGED_PAD1.0X1.5MM 89.15,84.09 r0 bottom value=Jmp_2_Bridged
K1 "Comment" RELAY_SPDT_RAYEX-L90S 15.26,43.347 r270 top value=J115F11CH5VDCS61.5U
K2 "Comment" "BIG PADS - RELAY_SPDT_SCHRACK-RT1-16A-FORMC_RM5MM" 4.655,77.137 r0 top value=J114FL1CS165VDC.41
K3 "Comment" "BIG PADS - RELAY_SPDT_SCHRACK-RT1-16A-FORMC_RM5MM" 4.775,92.082 r0 top value=J114FL1CS165VDC.41
PS1 "Comment" CONV_I7C4W008A120V-0C3-R 60.625,67.962 r270 bottom value=I7C4W008A120V-0C3-R
PS2 "Comment" CONV_I7C4W008A120V-0C3-R 45.395,52.562 r90 bottom value=I7C4W008A120V-0C3-R
PS3 "Comment" CONV_I3A4W008A033V-001-R 86.44,16.299 r270 top value=I3A4W008A033V-001-R
R1 "Comment" R_1206_3216METRIC 49.185,99.182 r0 top value=4.64k
R2 "Comment" R_1206_3216METRIC 56.337,17.994 r180 top value=28
R3 "Comment" R_1206_3216METRIC 36.44,91.587 r270 top value=1k
R4 "Comment" R_1206_3216METRIC 64.96,24.187 r90 top value=1k
R5 "Comment" R_1206_3216METRIC 122.682,53.43 r0 top value=28
R6 "Comment" R_1206_3216METRIC 59.093,111.457 r90 top value=10k
R7 "Comment" R_1206_3216METRIC 52.45,111.457 r90 top value=10k
R8 "Comment" R_1206_3216METRIC 45.808,111.457 r90 top value=10k
R9 "Comment" R_1206_3216METRIC 65.736,111.457 r90 top value=10k
R10 "Comment" R_1206_3216METRIC 72.378,111.457 r90 top value=10k
R11 "Comment" R_1206_3216METRIC 122.704,57.051 r0 top value=10k
R12 "Comment" R_1206_3216METRIC 122.568,38.623 r180 top value=10k
R13 "Comment" R_1206_3216METRIC 120.111,87.567 r0 top value=10k
R14 "Comment" R_1206_3216METRIC 120.111,85.167 r0 top value=10k
R15 "Comment" R_1206_3216METRIC 120.111,82.767 r0 top value=10k
R16 "Comment" R_1206_3216METRIC 120.111,89.967 r0 top value=10k
R17 "Comment" R_1206_3216METRIC 138.549,89.252 r180 top value=10k
R18 "Comment" R_1206_3216METRIC 138.549,96.552 r180 top value=10k
R19 "Comment" R_1206_3216METRIC 138.549,91.685 r180 top value=10k
R20 "Comment" R_1206_3216METRIC 138.549,94.118 r180 top value=10k
R21 "Comment" R_1206_3216METRIC 117.294,79.187 r180 top value=220k
R22 "Comment" R_1206_3216METRIC 122.506,79.187 r0 top value=10k
R23 "Comment" R_1206_3216METRIC 117.294,74.299 r180 top value=220k
R24 "Comment" R_1206_3216METRIC 122.506,74.299 r0 top value=10k
R25 "Comment" R_1206_3216METRIC 117.294,76.743 r180 top value=220k
R26 "Comment" R_1206_3216METRIC 122.506,76.743 r0 top value=10k
R27 "Comment" R_1206_3216METRIC 117.294,69.411 r180 top value=220k
R28 "Comment" R_1206_3216METRIC 122.506,69.411 r0 top value=10k
R29 "Comment" R_1206_3216METRIC 117.294,71.855 r180 top value=220k
R30 "Comment" R_1206_3216METRIC 122.506,71.855 r0 top value=10k
R31 "Comment" R_1206_3216METRIC 39.34,67.187 r0 top value=10k
R32 "Comment" R_1206_3216METRIC 52.431,105.321 r0 top value=10k
R33 "Comment" R_1206_3216METRIC 19.391,110.485 r90 top value=10k
R34 "Comment" R_1206_3216METRIC 115.09,51.937 r0 top value=10k
R35 "Comment" R_1206_3216METRIC 112.59,37.187 r90 top value=10k
R36 "Comment" R_1206_3216METRIC 112.31,87.388 r180 top value=1k
R37 "Comment" R_1206_3216METRIC 112.418,83.488 r180 top value=1k
R38 "Comment" R_1206_3216METRIC 108.63,101.026 r180 top value=1k
R39 "Comment" R_1206_3216METRIC 118.84,94.437 r0 top value=10k
R40 "Comment" RES_3540_TEC 3.302,37.759 r90 top value=180
RL1 "Comment" EE2-5NU 128.048,15.237 r270 top value=EE2-5NU
Rup1 "Comment" R_1206_3216METRIC 73.09,10.687 r90 top value=7.57k
SW1 "Comment" SW_TL3305BF260QG 108.619,94.298 r90 top value=SW_Push
SW2 "Comment" SW_TL3305BF260QG 76.343,63.856 r90 top value=SW_Push
TP1 "Comment" TESTPOINT_PAD_D1.0MM 120.14,60.387 r0 top value="KeySwitch IN"
TP2 "Comment" TESTPOINT_PAD_D1.0MM 119.74,12.687 r0 top value=TestPoint
TP3 "Comment" TESTPOINT_PAD_D1.0MM 106.54,12.687 r0 top value=TestPoint
TP4 "Comment" TESTPOINT_PAD_D1.0MM 65.44,30.287 r0 top value=TestPoint
TP5 "Comment" TESTPOINT_PAD_D1.0MM 70.54,30.187 r0 top value=TestPoint
U1 "Comment" MODULE_SCO915_CUSTOM_HEADERSTYLE 82.487,112.786 r0 top value=SC0915
U4 "Comment" HSOP-6J 114.79,30.537 r90 top value=R1560S501B-E2-FE
U5 "Comment" TSSOP-16_4.4X5MM_P0.65MM 129.329,88.443 r180 top value=74HC4051
U6 "Comment" SOT-23 70.132,58.468 r180 top value=MCP9700T-ETT
U7 "Comment" SOT-23 137.029,8.753 r90 top value=MCP9700T-ETT

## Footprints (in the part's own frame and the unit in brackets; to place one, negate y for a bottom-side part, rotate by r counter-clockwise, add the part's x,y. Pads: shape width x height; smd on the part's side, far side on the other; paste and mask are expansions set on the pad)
3557-10 [mm]
  rect 3x2.108 hole 0.8 slot 1.6 at 0 deg paste-2539.97 mask+0: 1(0,0)
  rrect100% 3x2.108 hole 0.8 slot 1.6 at 0 deg paste-2539.97 mask+0: 2(0,-3.404) 3(13.462,-3.404) 4(13.462,0)
  silkscreen extent -3.3,-5.19 16.76,1.79, body extent -3.37,-5.18 16.63,1.82, height 2.45
1843606 [mm]
  rect 2.5x2.5 hole 1.194 paste-2539.97 mask+0: 1(-3.5,0)
  round 2.5 hole 1.194 paste-2539.97 mask+0: 2(0,0)
  silkscreen extent -7.1,-3.12 2.58,4.38, body extent -5.93,-3.03 2.47,4.22, height 9.2
1924321 [mm]
  rrect100% 3x4 hole 1.4 paste-2539.97 mask+0: 1(-7.62,0) 2(-2.54,0) 3(2.54,0) 4(7.62,0)
  silkscreen extent -11.16,-3.82 11.16,3.8, body extent -11.13,-4.78 11.19,3.82, height 12
"BIG PADS - RELAY_SPDT_SCHRACK-RT1-16A-FORMC_RM5MM" [mm]
  rrect100% 2x4 hole 1.3 paste-2539.97 mask+0: 11(20.3,0) 11(20.3,7.5) 12(15.26,0) 12(15.26,7.5) 14(25.34,0) 14(25.34,7.5)
  rect 4x3 hole 1.3 paste-2539.97 mask+0: A1(0,0)
  rrect100% 4x3 hole 1.3 paste-2539.97 mask+0: A2(0,7.5)
  silkscreen extent -2.75,-3 26.85,10.3, body extent -2.34,-2.77 26.85,10.19, height 12
C_1206_3216METRIC [mm]
  rrect22% 1.15x1.8 smd mask+0: 1(-1.475,0) 2(1.475,0)
  silkscreen extent -0.71,-0.91 0.71,0.91
C_1210_3225METRIC [mm]
  rrect22% 1.15x2.7 smd mask+0: 1(-1.475,0) 2(1.475,0)
  silkscreen extent -0.71,-1.36 0.71,1.36
CONV_I3A4W008A033V-001-R [mm]
  rect 1.83x1.83 hole 1.22 paste-2539.97 mask+0.102: 1(-6.85,7.62)
  round 1.83 hole 1.22 paste-2539.97 mask+0.102: 2(-6.85,0) 3(-6.85,-7.62) 6(6.75,0) 7(6.75,3.81)
  round 2.655 hole 1.77 paste-2539.97 mask+0.102: 4(6.75,-7.62) 8(6.75,7.62)
  silkscreen extent -10.35,-11.7 9.55,11.7, body extent -9.51,-11.72 9.54,11.65, height 9.76
CONV_I7C4W008A120V-0C3-R [mm]
  rect 3x3 hole 1.22 paste-2539.97 mask+0: 1(0,0)
  round 2.5 hole 1.22 paste-2539.97 mask+0: 2(0,7.62) 5(-27.94,11.43) 6(-27.94,7.62) 7(-27.94,3.81) 32(-12.07,15.24) 34(-15.88,15.24)
  round 3 hole 1.22 paste-2539.97 mask+0: 3(0,15.24)
  round 3.5 hole 1.77 paste-2539.97 mask+0: 4(-27.94,15.24) 8(-27.94,0)
  silkscreen extent -31.54,-10.8 3.91,26.03, body extent -31.5,-10.79 2.54,26.04, height 13.46
CP_ELEC_10X12.6 [mm]
  rrect13% 4.4x1.9 smd mask+0: 1(-4.35,0) 2(4.35,0)
  silkscreen extent -6.75,-5.26 5.26,5.26
CUI_PJ-063BH [mm]
  rrect100% 3x5 hole 3 slot 1 at 0 deg paste-2539.97 mask+0: 1(0,0)
  rrect100% 3x4.5 hole 2.3 slot 1 at 0 deg paste-2539.97 mask+0: 2(6,0)
  rrect100% 4x2.5 hole 1 slot 2.5 at 0 deg paste-2539.97 mask+0: S1(7,4.5) S2(7,-4.5)
  round 1.6 hole 1.6 paste-2539.97 mask+0: Un1(9,0)
  silkscreen extent -2,-5 12,5, body extent -0.96,-5.52 12.04,4.78, height 9
D_SMA [mm]
  rrect14% 2.5x1.8 smd mask+0: 1(-2,0) 2(2,0)
  silkscreen extent -3.51,-1.65 2,1.65
D_SOD-123F [mm]
  rrect23% 1.1x1.1 smd mask+0: 1(-1.4,0) 2(1.4,0)
  silkscreen extent -2.21,-1 1.65,1
EE2-5NU [mm]
  rect 1.1x3 smd mask+0: +(-6.198,-3.728) -(-6.193,3.55) C1(1.422,-3.728) C2(1.427,3.55) NC1(-1.118,-3.728) NC2(-1.113,3.55) NO1(3.962,-3.728) NO2(3.967,3.55)
  silkscreen extent -7.25,-3.84 7.76,3.66, body extent -7.52,-4.85 7.48,4.65, height 10
FUSC9830X318N [mm]
  rect 2.62x3.2 smd mask+0: 1(-4.047,0) 2(4.047,0)
  silkscreen extent -2.47,-1.52 2.47,1.52, body extent -4.85,-1.63 4.95,1.55, height 2.83
FUSE_1206_3216METRIC_PAD1.42X1.75MM_HANDSOLDER [mm]
  rrect18% 1.425x1.75 smd mask+0: 1(-1.488,0) 2(1.488,0)
  silkscreen extent -0.6,-0.91 0.6,0.91
HSOP-6J [mm]
  rect 0.6x1.05 smd mask+0: 1(-1.93,-2.65) 3(1.88,-2.65) 4(1.88,2.7) 6(-1.93,2.7)
  rect 1.9x1.05 smd mask+0: 2(-0.025,-2.65) 5(-0.025,2.7)
  silkscreen extent -2.62,-1.9 2.5,2, body extent -2.48,-3.03 2.54,2.97, height 1.65
LED_1206_3216METRIC [mm]
  rrect20% 1.25x1.75 smd mask+0: 1(-1.4,0) 2(1.4,0)
  silkscreen extent -2.28,-1.13 1.6,1.13
MODULE_SCO915_CUSTOM_HEADERSTYLE [mm]
  rect 1.7x1.7 hole 1 paste-2539.97 mask+0: 1(0.853,-0.859) 40(18.633,-0.859)
  rrect100% 1.7x1.7 hole 1 paste-2539.97 mask+0: 2(0.853,-3.399) 3(0.853,-5.939) 4(0.853,-8.479) 5(0.853,-11.019) 6(0.853,-13.559) 7(0.853,-16.099) 8(0.853,-18.639) 9(0.853,-21.179) 10(0.853,-23.719) 11(0.853,-26.259) 12(0.853,-28.799) 13(0.853,-31.339) 14(0.853,-33.879) 15(0.853,-36.419) 16(0.853,-38.959) 17(0.853,-41.499) 18(0.853,-44.039) 19(0.853,-46.579) 20(0.853,-49.119) 21(18.633,-49.119) 22(18.633,-46.579) 23(18.633,-44.039) 24(18.633,-41.499) 25(18.633,-38.959) 26(18.633,-36.419) 27(18.633,-33.879) 28(18.633,-31.339) 29(18.633,-28.799) 30(18.633,-26.259) 31(18.633,-23.719) 32(18.633,-21.179) 33(18.633,-18.639) 34(18.633,-16.099) 35(18.633,-13.559) 36(18.633,-11.019) 37(18.633,-8.479) 38(18.633,-5.939) 39(18.633,-3.399)
  silkscreen extent -0.48,-50.45 19.96,0.47
MOUNTINGHOLE_3.2MM_M3_DIN965_PAD [mm]
  round 5.6 hole 3.2 paste-2539.97 mask+0: 1(0,0)
PINHEADER_1X02_P2.54MM_VERTICAL [mm]
  rect 1.7x1.7 hole 1 paste-2539.97 mask+0: 1(0,0)
  rrect100% 1.7x1.7 hole 1 paste-2539.97 mask+0: 2(0,-2.54)
  silkscreen extent -1.33,-3.87 1.33,1.33
PINHEADER_1X04_P2.54MM_VERTICAL [mm]
  rect 1.7x1.7 hole 1 paste-2539.97 mask+0: 1(0,0)
  rrect100% 1.7x1.7 hole 1 paste-2539.97 mask+0: 2(0,-2.54) 3(0,-5.08) 4(0,-7.62)
  silkscreen extent -1.33,-8.95 1.33,1.33
PINHEADER_2X06_P2.54MM_VERTICAL [mm]
  rect 1.7x1.7 hole 1 paste-2539.97 mask+0: 1(0,0)
  rrect100% 1.7x1.7 hole 1 paste-2539.97 mask+0: 2(2.54,0) 3(0,-2.54) 4(2.54,-2.54) 5(0,-5.08) 6(2.54,-5.08) 7(0,-7.62) 8(2.54,-7.62) 9(0,-10.16) 10(2.54,-10.16) 11(0,-12.7) 12(2.54,-12.7)
  silkscreen extent -1.33,-14.03 3.87,1.33
PINHEADER_2X20_P2.54MM_HORIZONTAL [mm]
  rect 1.7x1.7 hole 1 paste-2539.97 mask+0: 1(0,0)
  rrect100% 1.7x1.7 hole 1 paste-2539.97 mask+0: 2(2.54,0) 3(0,-2.54) 4(2.54,-2.54) 5(0,-5.08) 6(2.54,-5.08) 7(0,-7.62) 8(2.54,-7.62) 9(0,-10.16) 10(2.54,-10.16) 11(0,-12.7) 12(2.54,-12.7) 13(0,-15.24) 14(2.54,-15.24) 15(0,-17.78) 16(2.54,-17.78) 17(0,-20.32) 18(2.54,-20.32) 19(0,-22.86) 20(2.54,-22.86) 21(0,-25.4) 22(2.54,-25.4) 23(0,-27.94) 24(2.54,-27.94) 25(0,-30.48) 26(2.54,-30.48) 27(0,-33.02) 28(2.54,-33.02) 29(0,-35.56) 30(2.54,-35.56) 31(0,-38.1) 32(2.54,-38.1) 33(0,-40.64) 34(2.54,-40.64) 35(0,-43.18) 36(2.54,-43.18) 37(0,-45.72) 38(2.54,-45.72) 39(0,-48.26) 40(2.54,-48.26)
  silkscreen extent -1.27,-49.59 12.64,1.33, body extent -1.14,-59.18 22.16,10.92, height 8.5
PINHEADER_2X20_P2.54MM_VERTICAL [mm]
  rect 1.7x1.7 hole 1 paste-2539.97 mask+0: 1(0,0)
  rrect100% 1.7x1.7 hole 1 paste-2539.97 mask+0: 2(2.54,0) 3(0,-2.54) 4(2.54,-2.54) 5(0,-5.08) 6(2.54,-5.08) 7(0,-7.62) 8(2.54,-7.62) 9(0,-10.16) 10(2.54,-10.16) 11(0,-12.7) 12(2.54,-12.7) 13(0,-15.24) 14(2.54,-15.24) 15(0,-17.78) 16(2.54,-17.78) 17(0,-20.32) 18(2.54,-20.32) 19(0,-22.86) 20(2.54,-22.86) 21(0,-25.4) 22(2.54,-25.4) 23(0,-27.94) 24(2.54,-27.94) 25(0,-30.48) 26(2.54,-30.48) 27(0,-33.02) 28(2.54,-33.02) 29(0,-35.56) 30(2.54,-35.56) 31(0,-38.1) 32(2.54,-38.1) 33(0,-40.64) 34(2.54,-40.64) 35(0,-43.18) 36(2.54,-43.18) 37(0,-45.72) 38(2.54,-45.72) 39(0,-48.26) 40(2.54,-48.26)
  silkscreen extent -1.33,-49.59 3.87,1.33
PINSOCKET_2X05_P2.54MM_VERTICAL [mm]
  rect 1.7x1.7 hole 1 paste-2539.97 mask+0: 1(0,0)
  rrect100% 1.7x1.7 hole 1 paste-2539.97 mask+0: 2(-2.54,0) 3(0,-2.54) 4(-2.54,-2.54) 5(0,-5.08) 6(-2.54,-5.08) 7(0,-7.62) 8(-2.54,-7.62) 9(0,-10.16) 10(-2.54,-10.16)
  silkscreen extent -3.87,-11.49 1.33,1.33
POWERDI5_DIO [mil]
  rect 39x45 smd mask+0: 1(-36.22,-115.5) 2(36.22,-115.5)
  rect 122x205 smd mask+0: 3(0,41.5)
  silkscreen extent -84,-112 84,228, body extent -77,-128 81,132, height 47
R_1206_3216METRIC [mm]
  rrect22% 1.125x1.75 smd mask+0: 1(-1.462,0) 2(1.462,0)
  silkscreen extent -0.73,-0.91 0.73,0.91
RELAY_SPDT_RAYEX-L90S [mm]
  rrect100% 6x5 hole 2.5 paste-2539.97 mask+0: 11(15.2,8.9)
  rrect100% 5x6 hole 2.5 paste-2539.97 mask+0: 12(25.34,-8.9) 14(17.74,-8.9)
  rrect25% 3x3 hole 1.1 paste-2539.97 mask+0: A1(2.54,5.1)
  round 3 hole 1.1 paste-2539.97 mask+0: A2(2.54,-5.1)
  silkscreen extent -4.07,-14.31 27.95,13.31, body extent -4.47,-14.29 27.58,12.71, height 20
RES_3540_TEC [mil]
  rect 87x173 smd mask+0: 1(-108,0) 2(108,0)
  silkscreen extent -52,-92 52,92, body extent -143,-86 145,86, height 47
SOLDERJUMPER-2_P1.3MM_BRIDGED_PAD1.0X1.5MM [mm]
  rect 1x1.5 smd paste-1.5 mask+0: 1(0.65,0) 2(-0.65,0)
  F.Cu region: -0.25,-0.3 0.25,-0.3 0.25,0.3 -0.25,0.3
  silkscreen extent -1.4,-1 1.4,1
SOT95P237X112-3N [mm]
  rect 1.3x0.6 smd mask+0: 1(-1.05,0.95) 2(-1.05,-0.95) 3(1.05,0)
  silkscreen extent -1.7,-1.46 0.05,1.5
SOT-23 [mm]
  rrect25% 1.475x0.6 smd mask+0: 1(-0.937,0.95) 2(-0.937,-0.95) 3(0.937,0)
  silkscreen extent -1.68,-1.56 0.65,1.56
SW_TL3305BF260QG [mm]
  rect 1.6x1.4 smd mask+0: 1(-3.6,-1.5) 1(3.6,-1.5) 2(-3.6,1.5) 2(3.6,1.5)
  silkscreen extent -5.1,-2.25 2.25,2.25, body extent -3.72,-2.25 3.78,2.25, height 5
TESTPOINT_PAD_D1.0MM [mm]
  round 1 smd paste-1 mask+0: 1(0,0)
  silkscreen extent -0.7,-0.7 0.7,0.7
TSSOP-16_4.4X5MM_P0.65MM [mm]
  rrect25% 1.475x0.4 smd mask+0: 1(-2.863,2.275) 2(-2.863,1.625) 3(-2.863,0.975) 4(-2.863,0.325) 5(-2.863,-0.325) 6(-2.863,-0.975) 7(-2.863,-1.625) 8(-2.863,-2.275) 9(2.863,-2.275) 10(2.863,-1.625) 11(2.863,-0.975) 12(2.863,-0.325) 13(2.863,0.325) 14(2.863,0.975) 15(2.863,1.625) 16(2.863,2.275)
  silkscreen extent -3.6,-2.74 2.2,2.74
